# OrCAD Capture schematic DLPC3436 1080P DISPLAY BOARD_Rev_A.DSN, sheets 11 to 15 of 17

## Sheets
11 P15: Actuator Power: size D
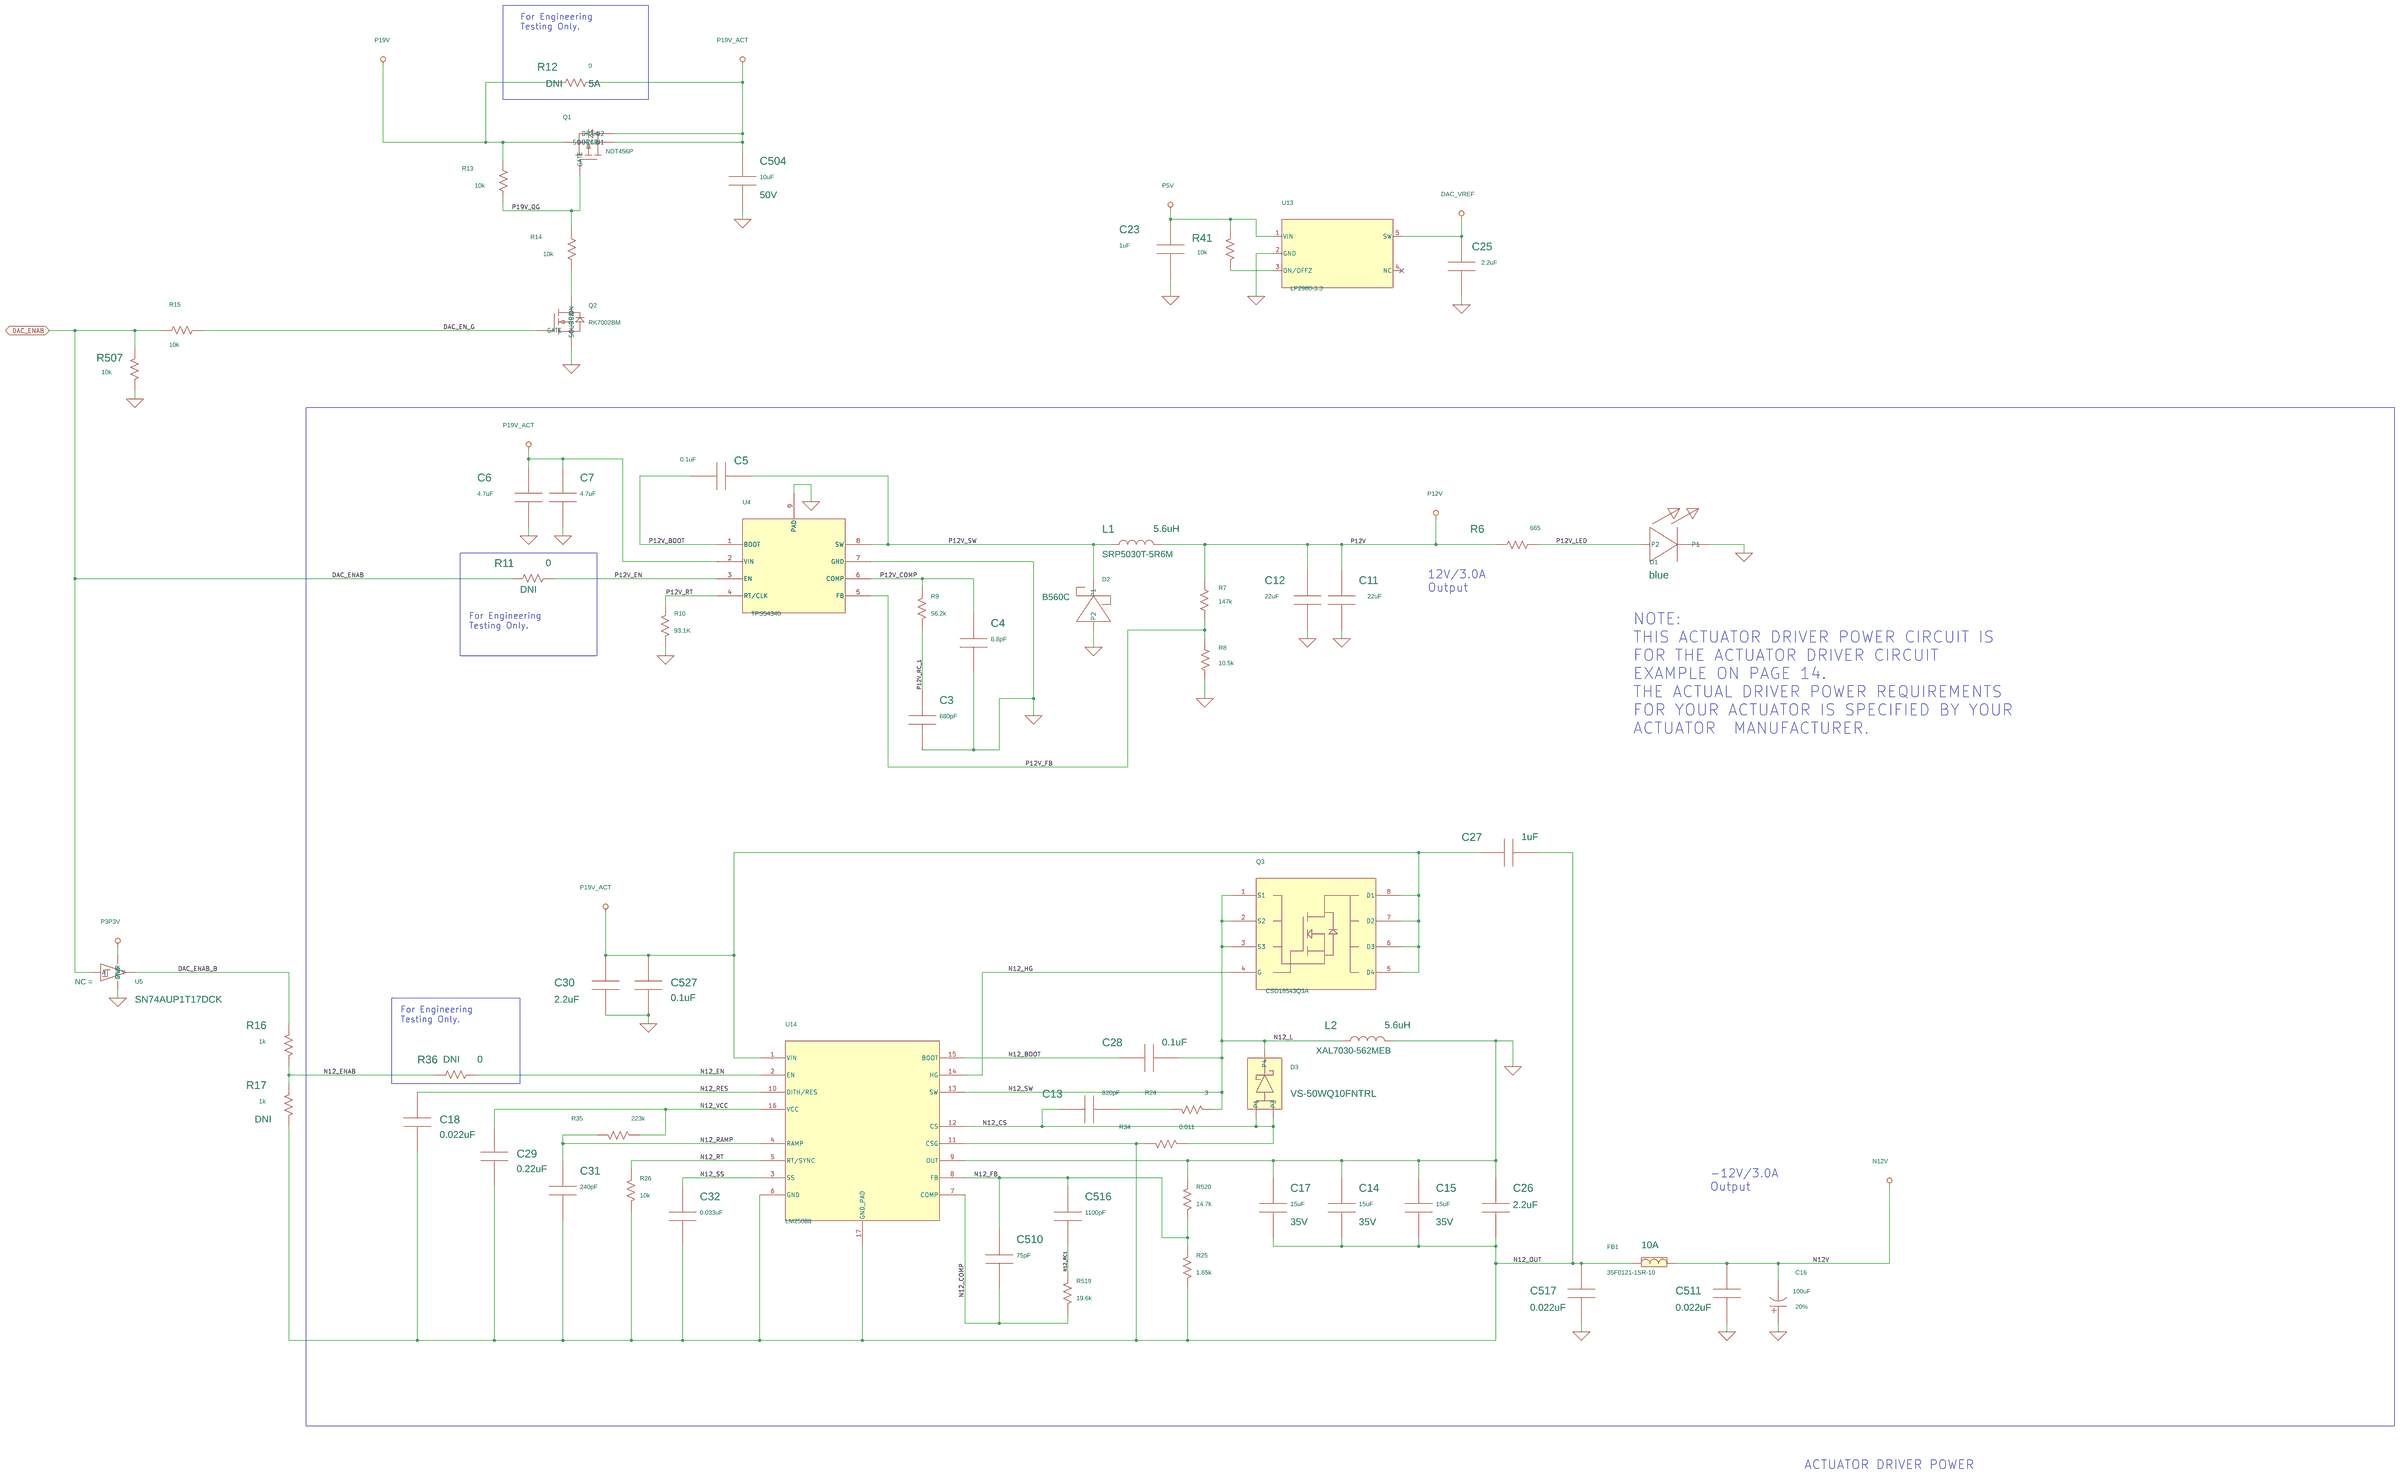
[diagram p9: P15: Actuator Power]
12 P06: Frame Buffer Memory: size D
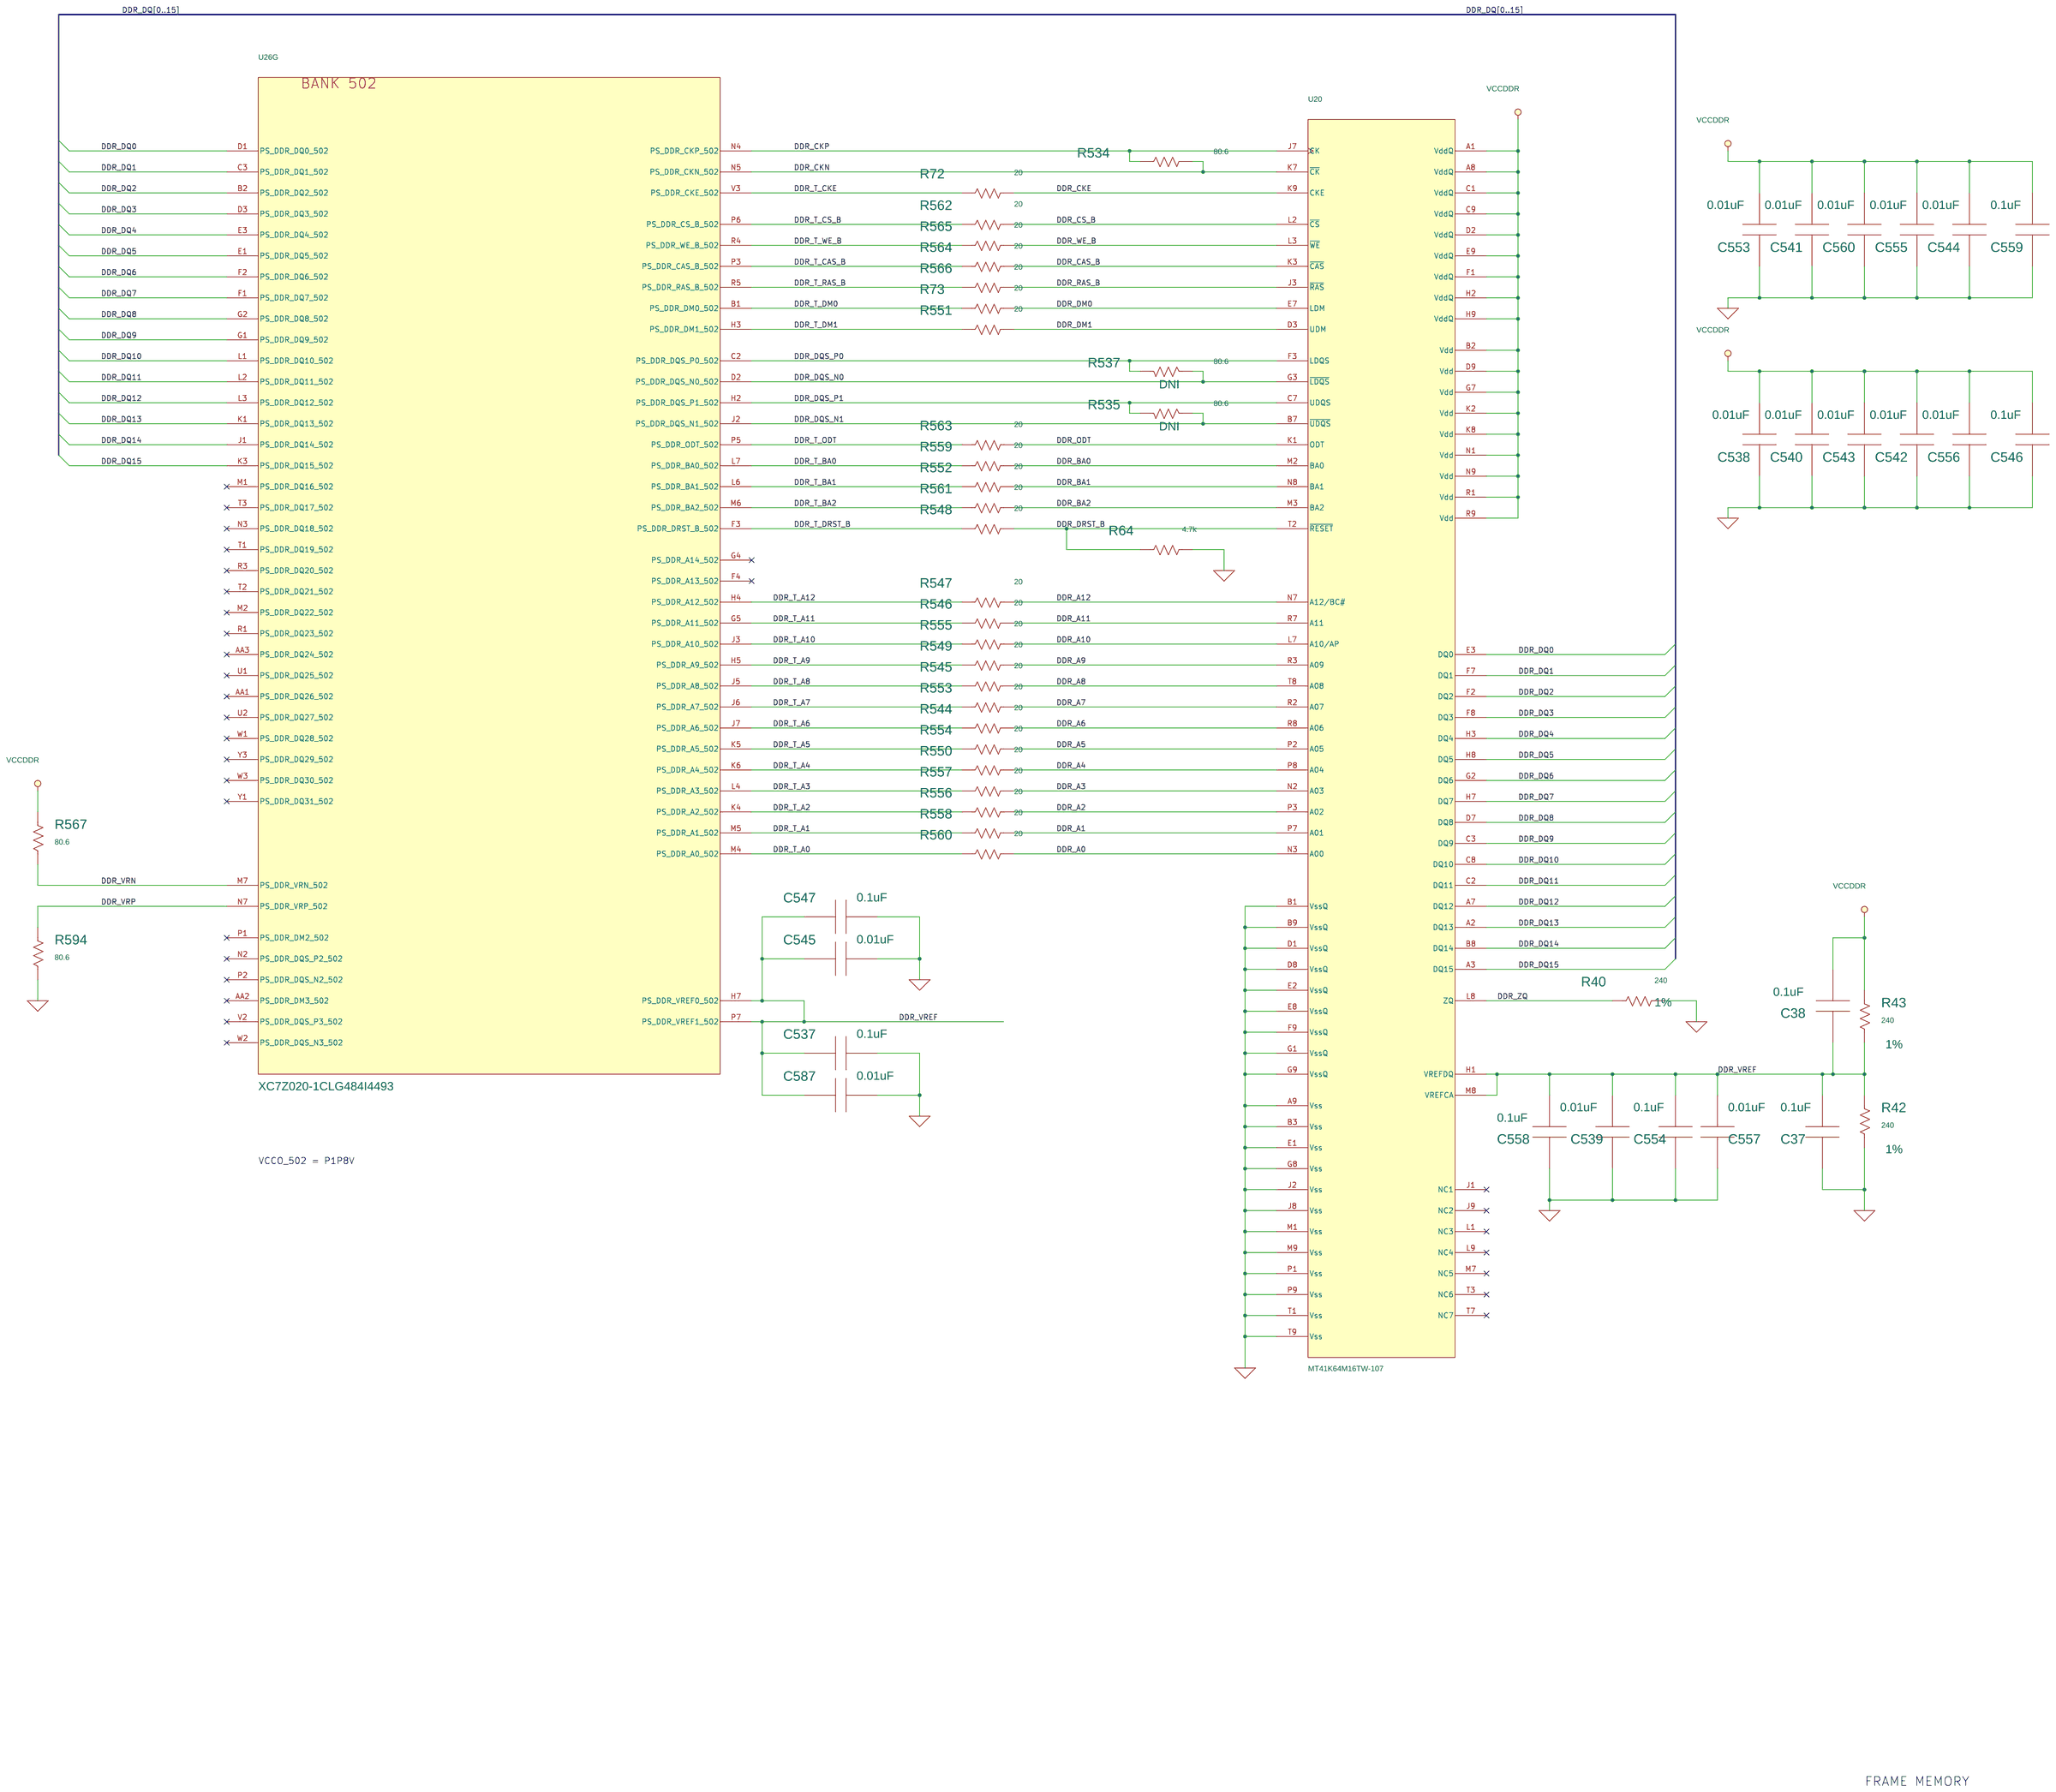
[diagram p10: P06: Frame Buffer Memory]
13 P05: FPGA PDATA Interface: size D
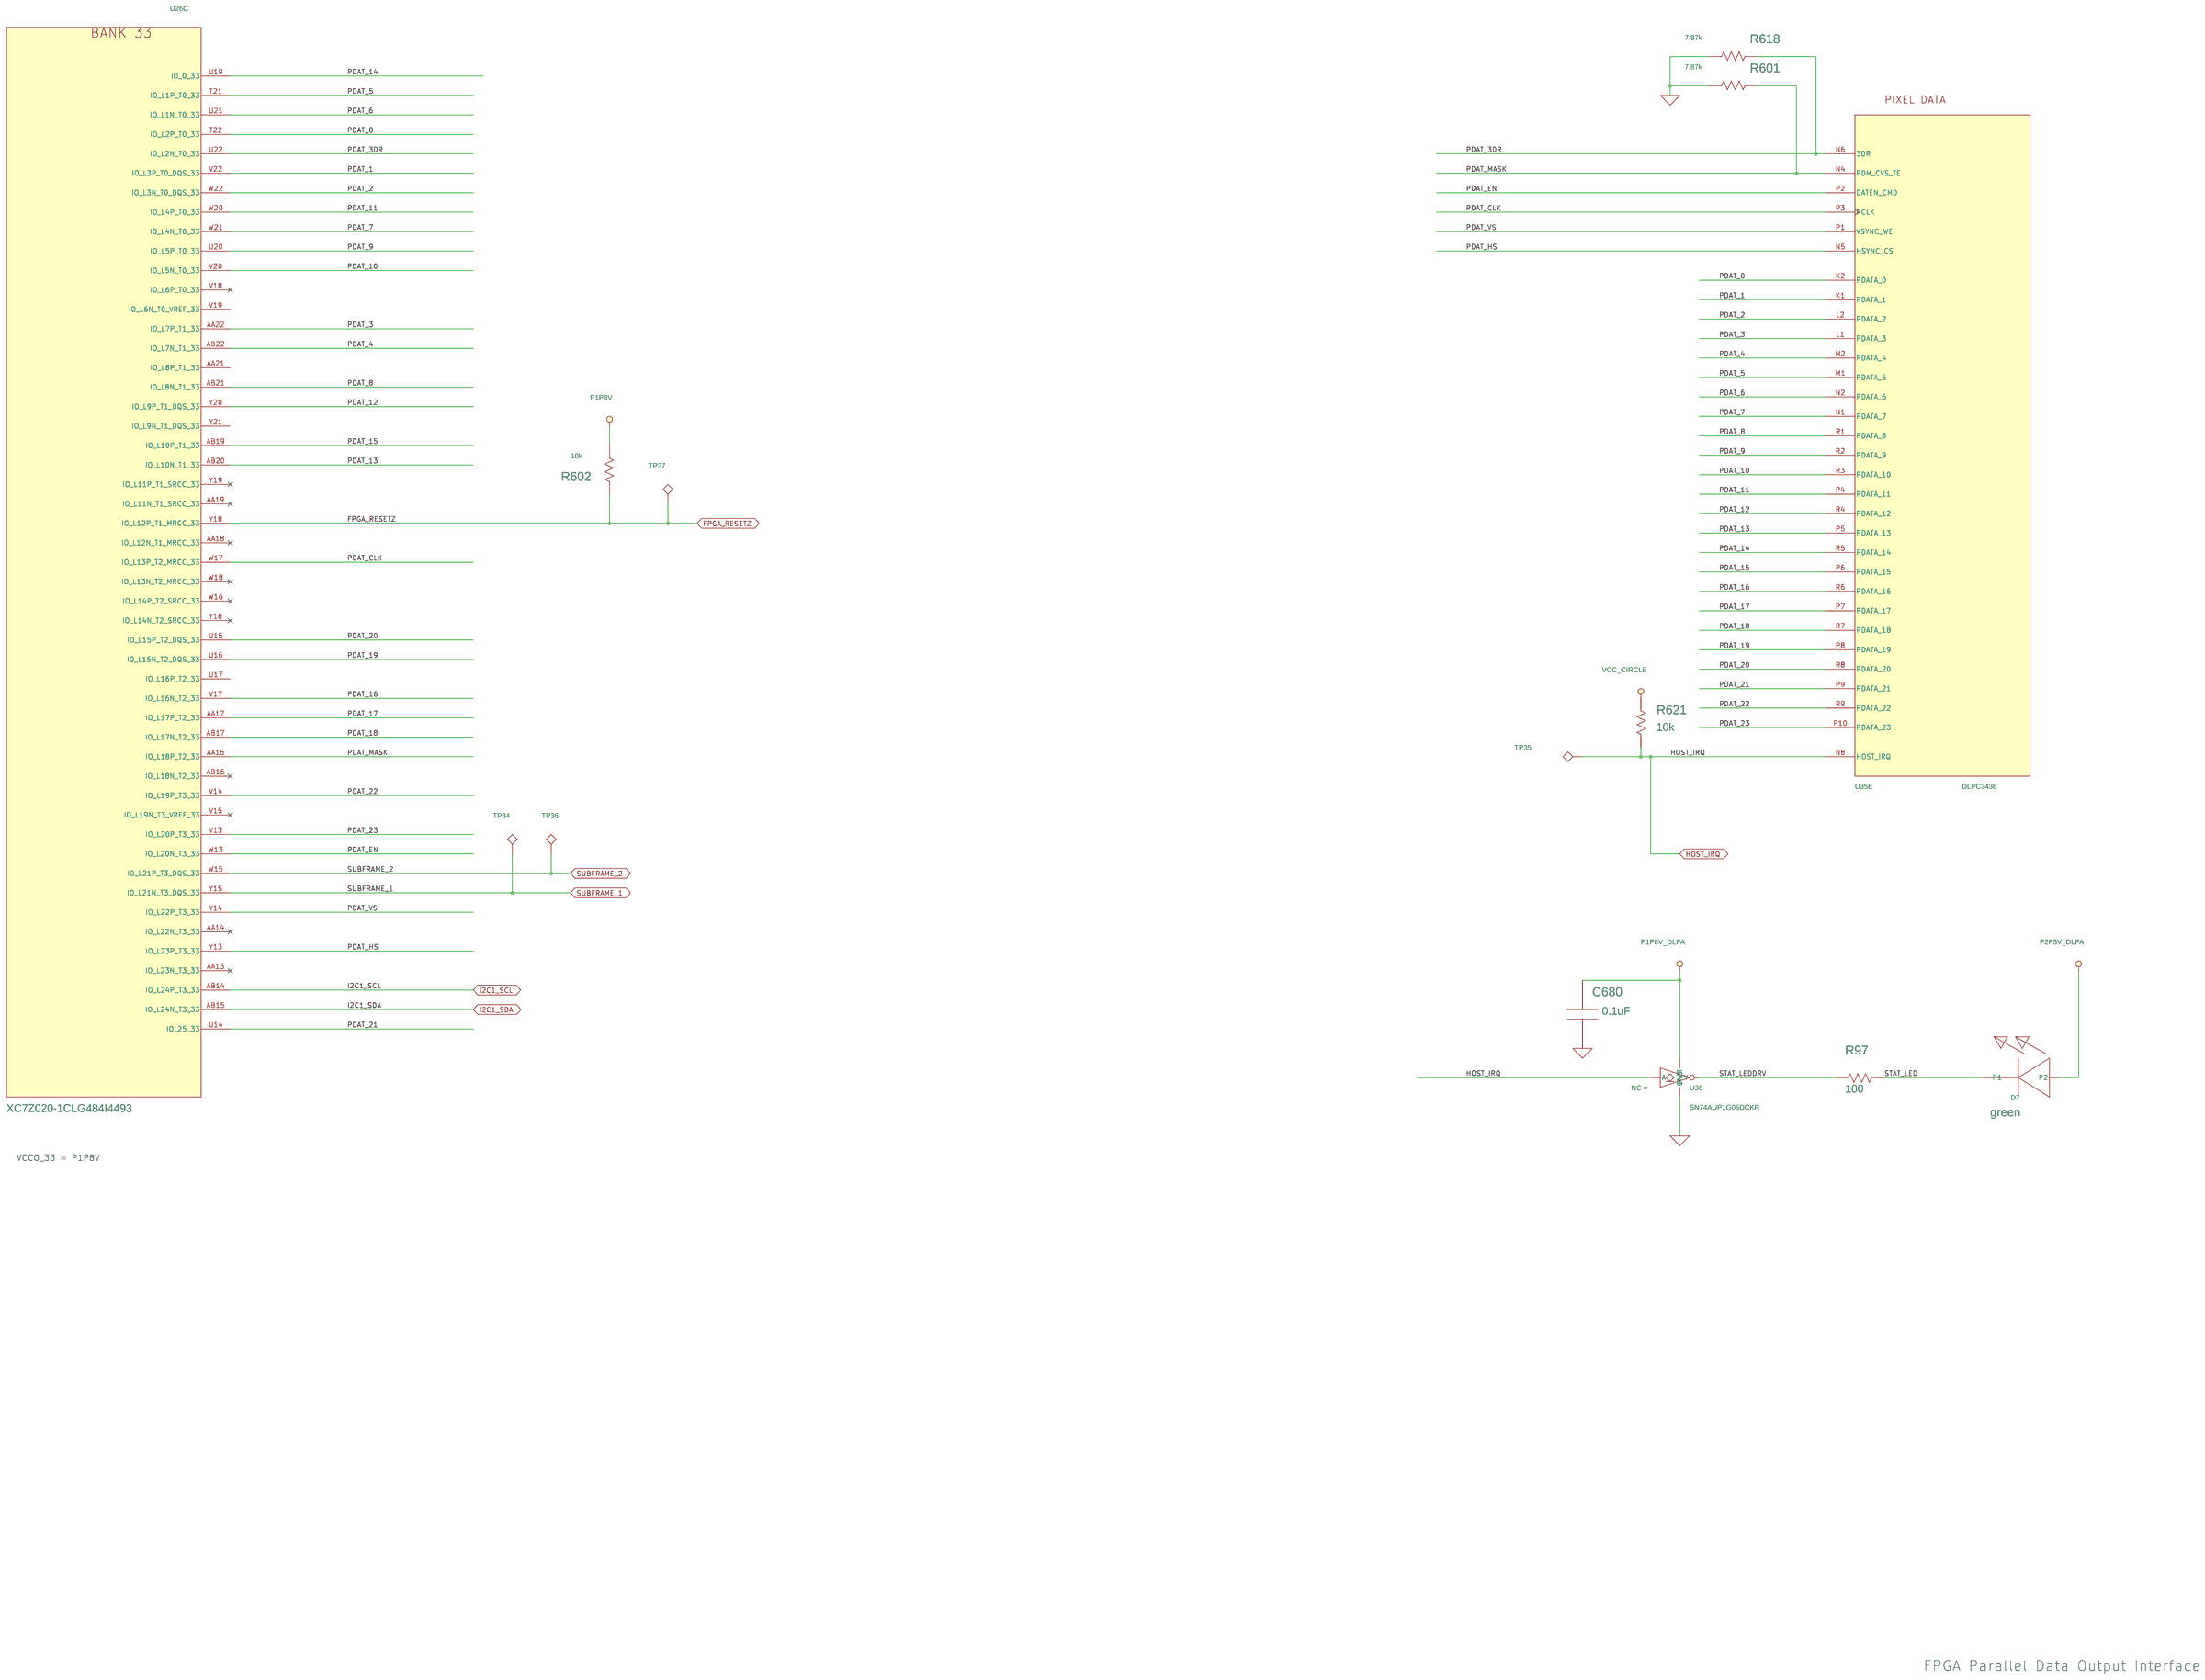
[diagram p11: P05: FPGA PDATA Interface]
14 P04: FPD-Link Video Input: size D
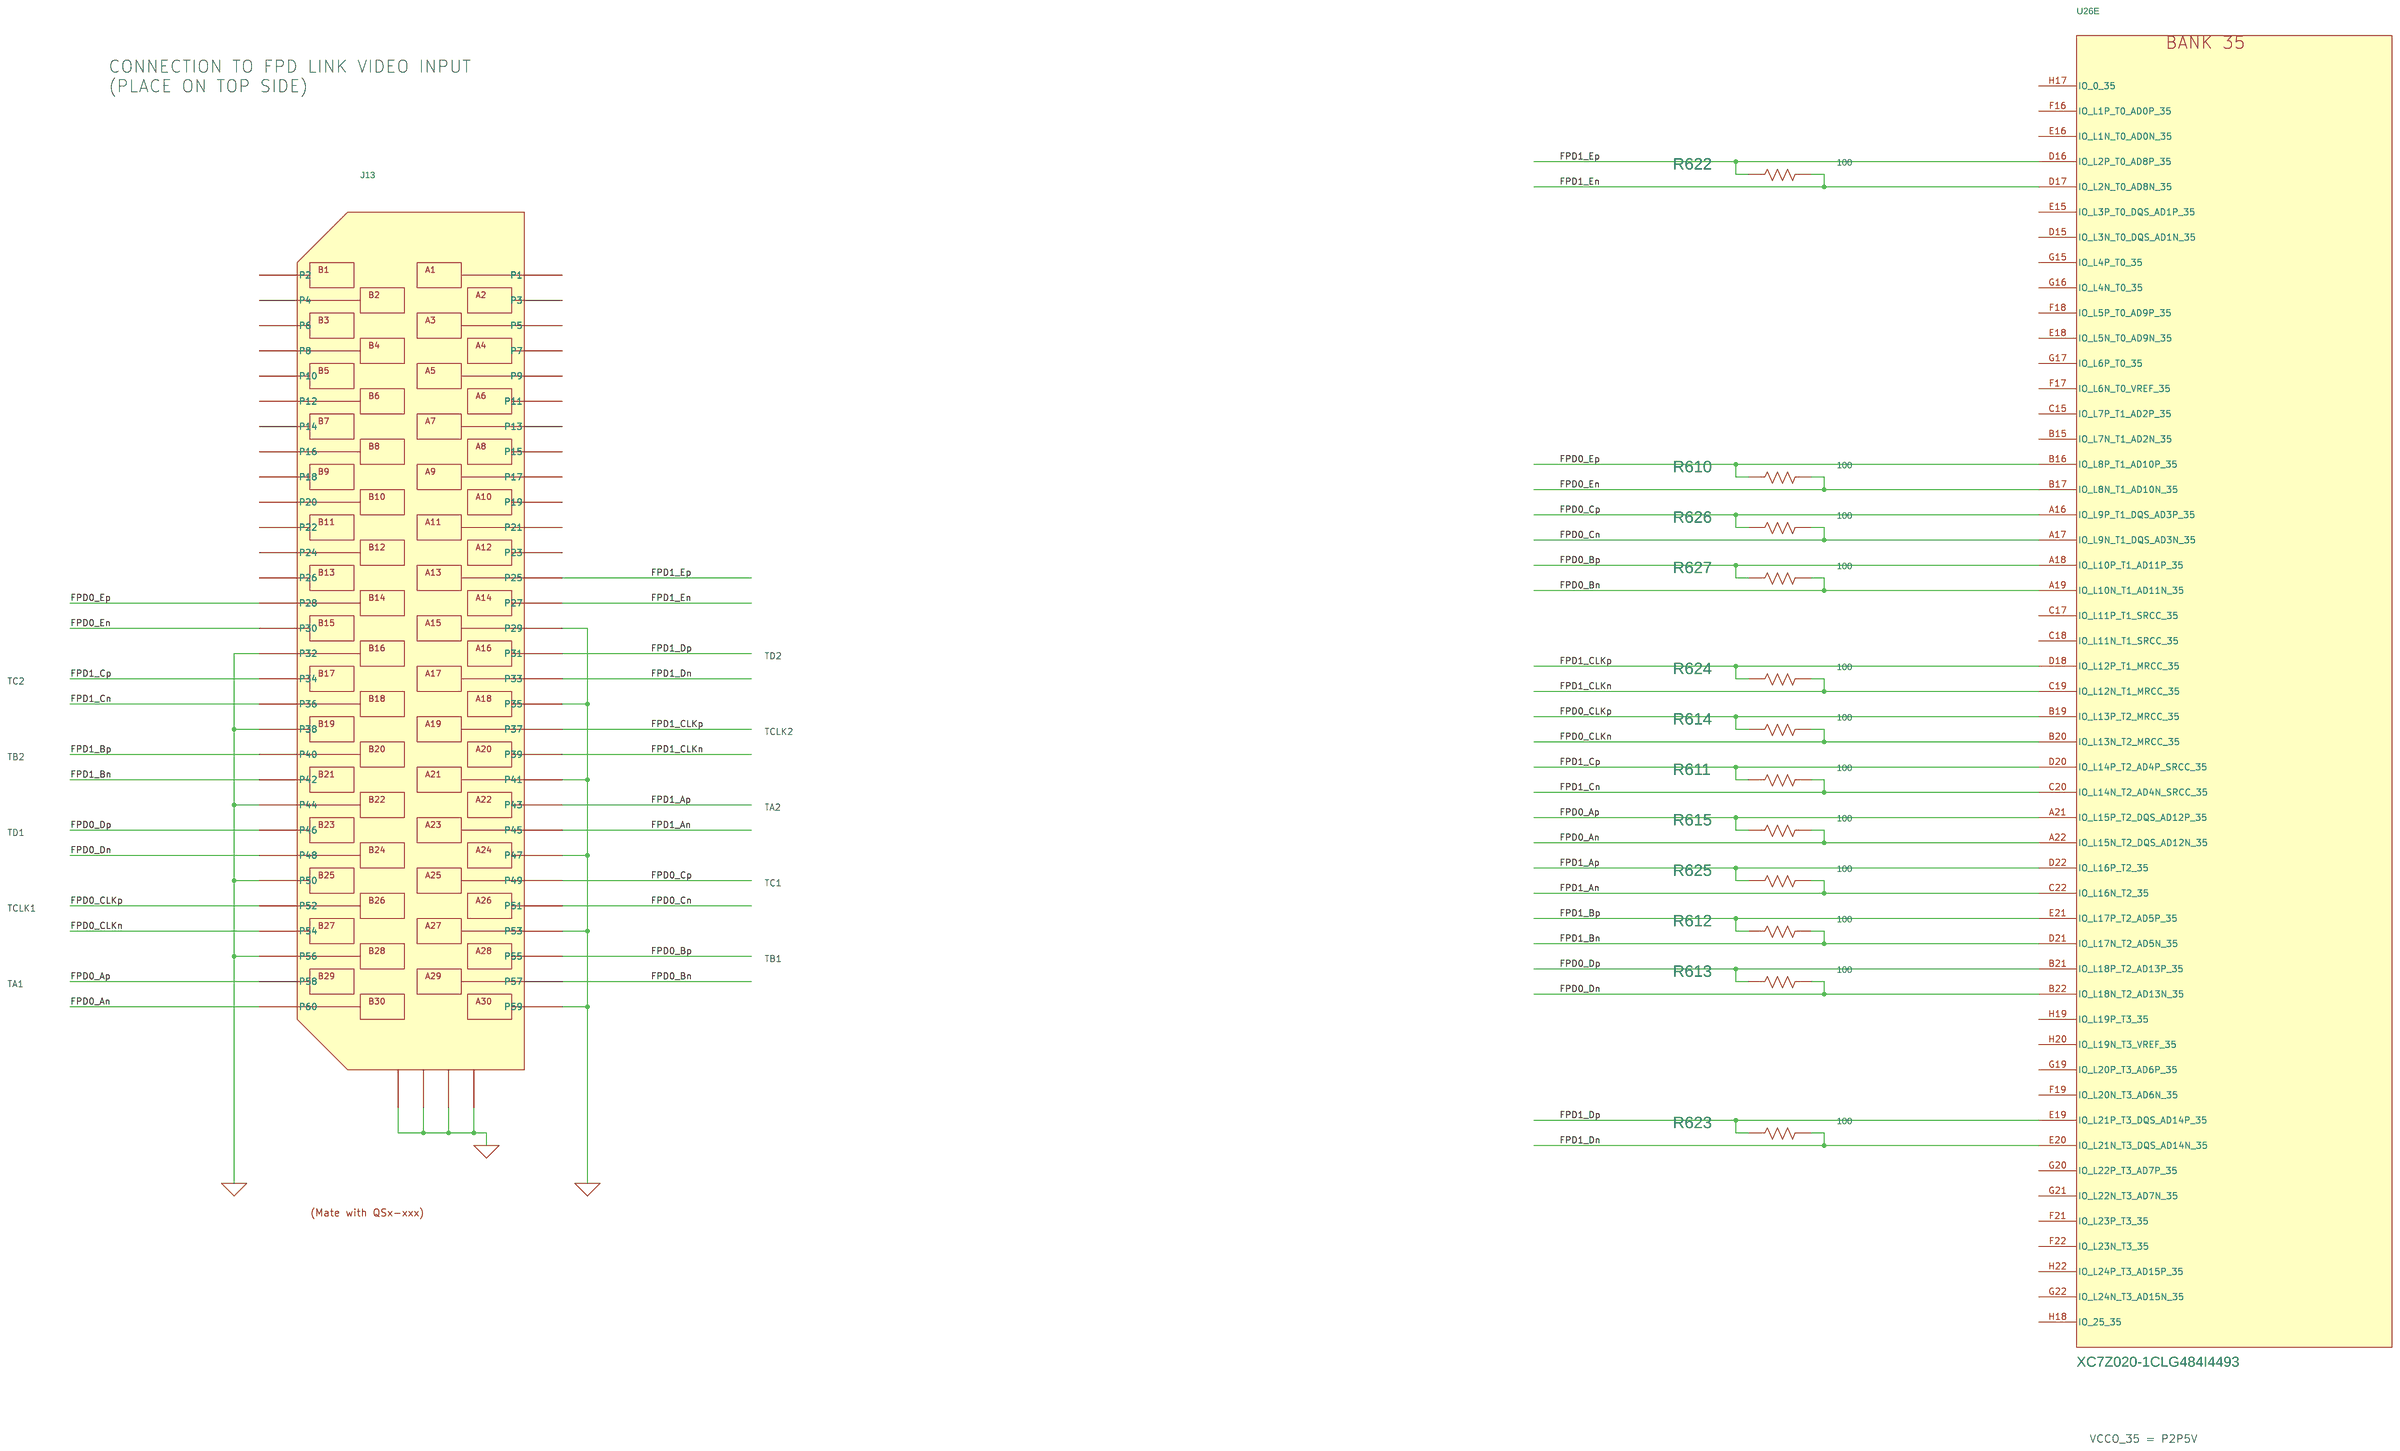
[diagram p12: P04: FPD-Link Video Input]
15 P09: DLPC3436 ASIC & Flash: size D
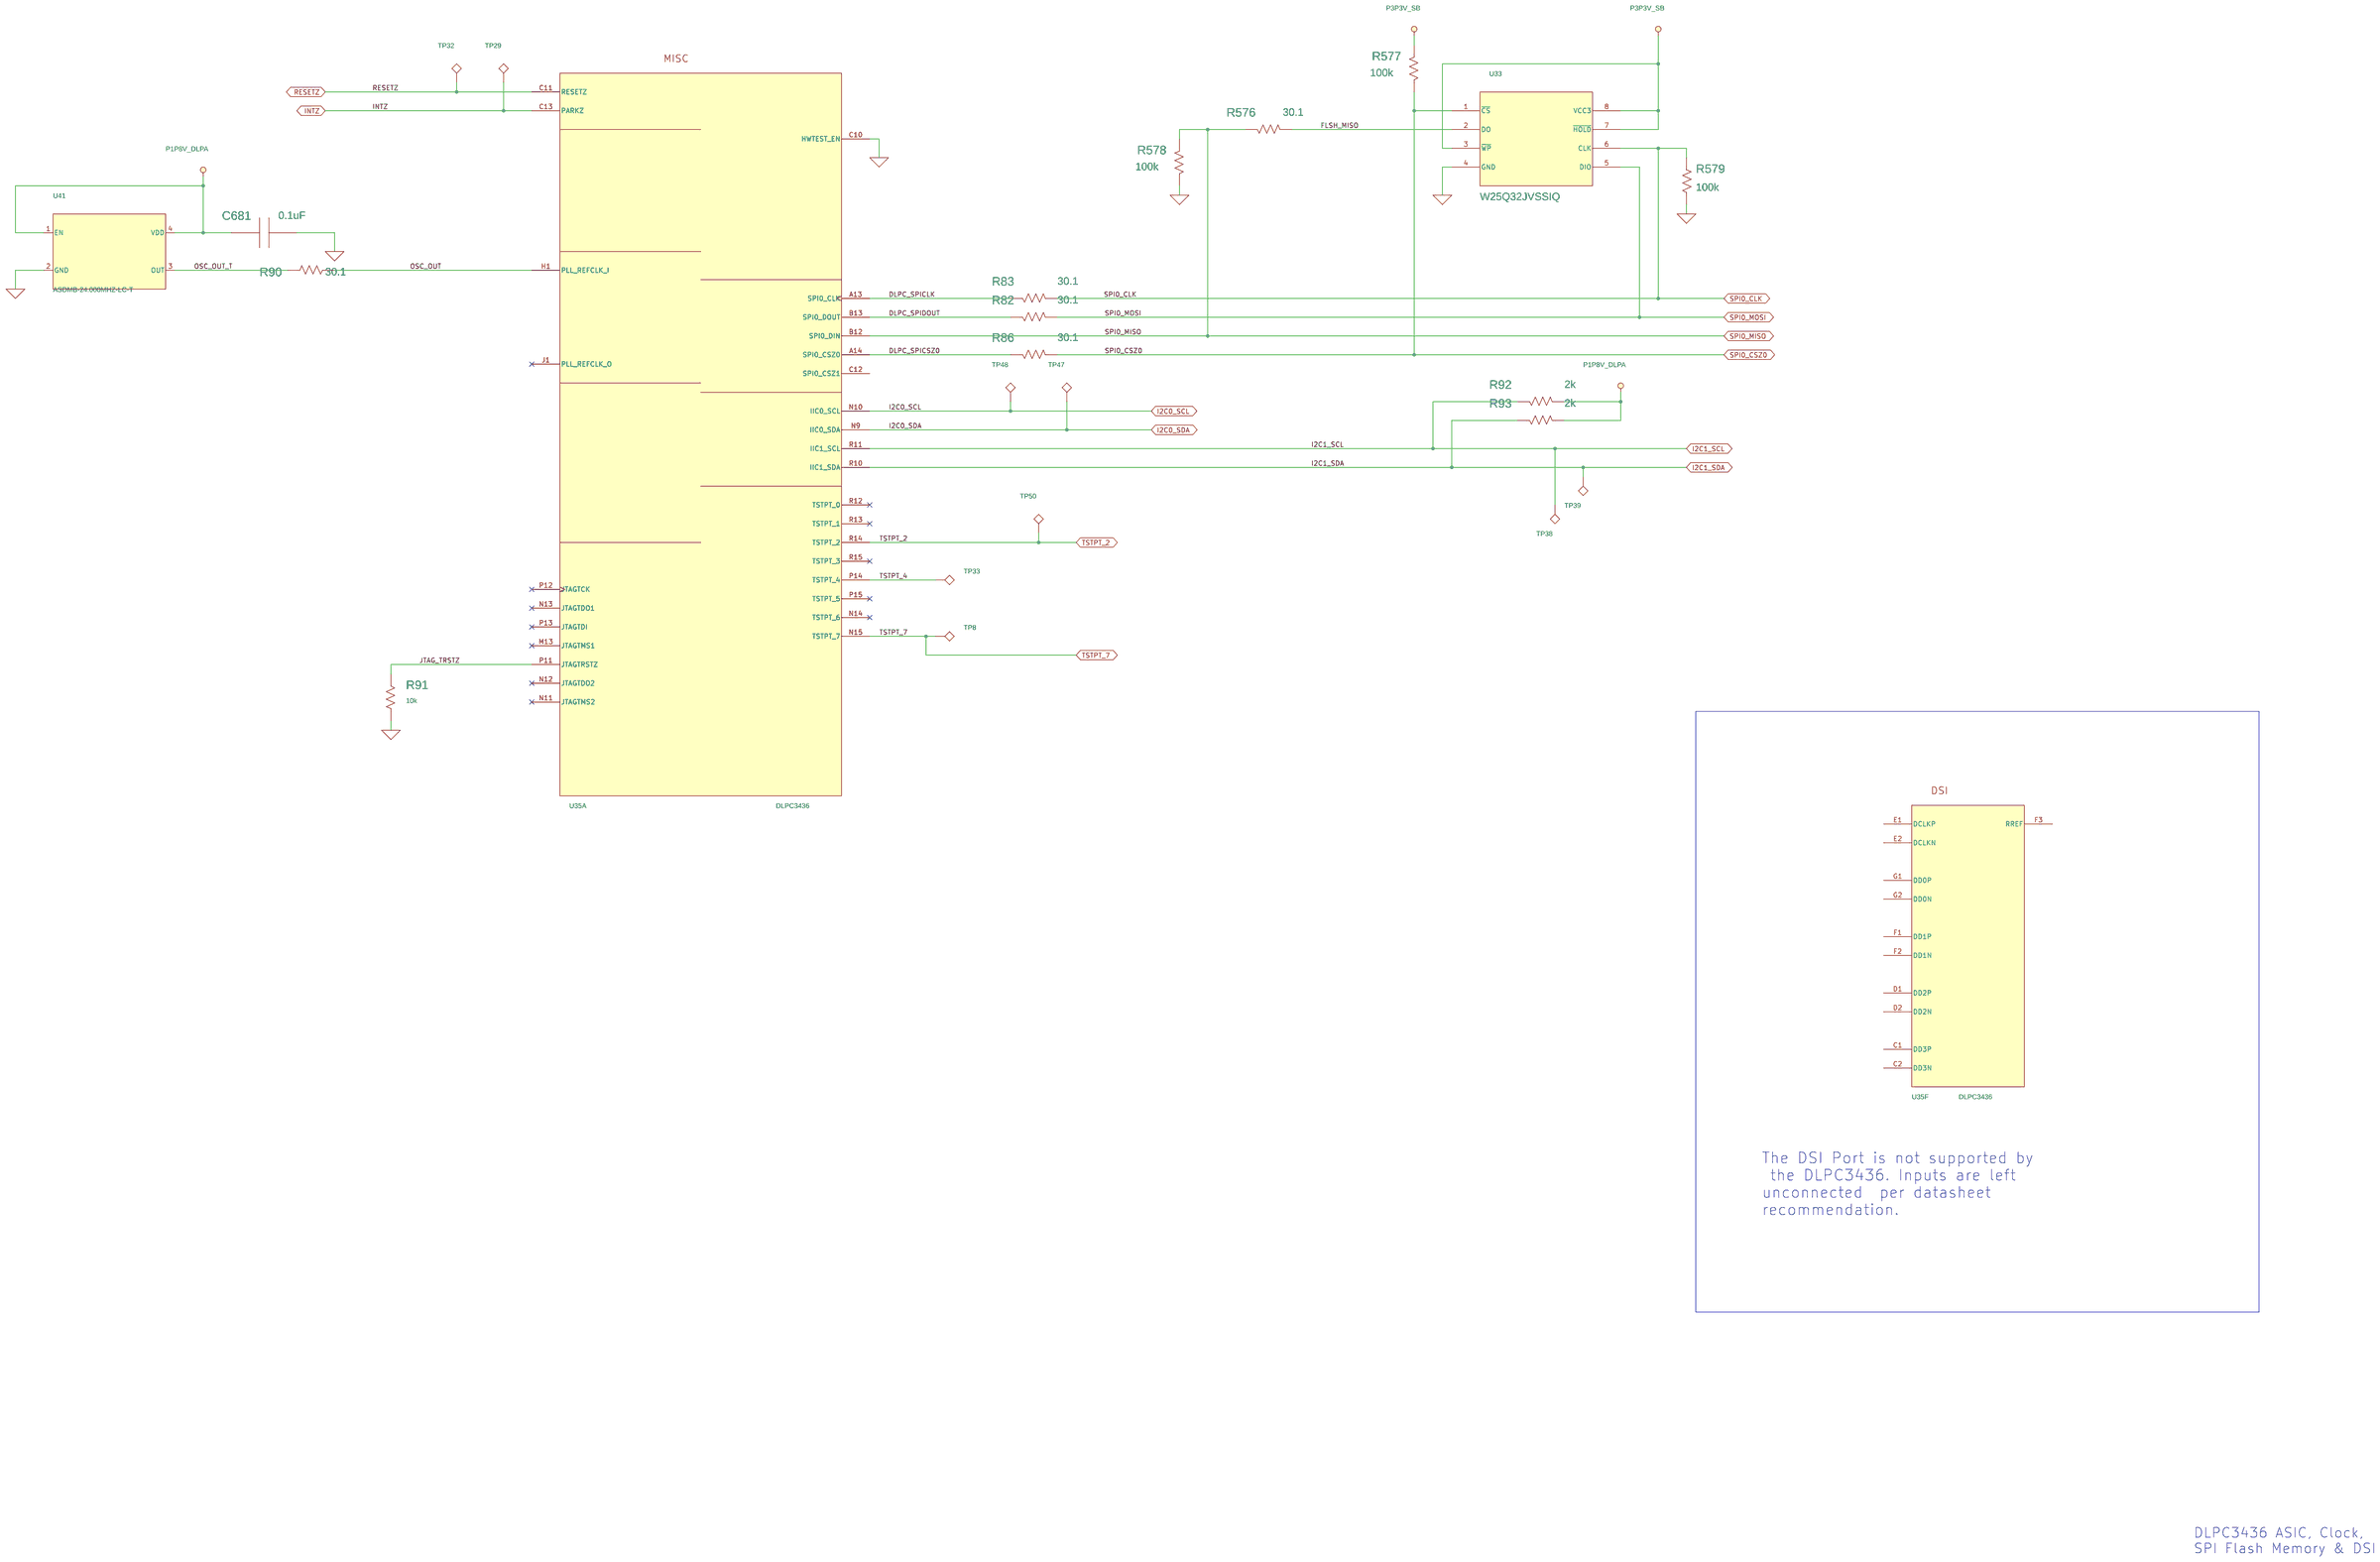
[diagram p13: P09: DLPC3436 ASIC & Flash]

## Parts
sheet P03: Parallel Video Input
U26  XC7Z020-1CLG484I4493  [Xilinx_CLG484]  (sections A,B,C,D,E,F,G,H,I,J)
sheet P04: FPD-Link Video Input
J13  QTH-030-02-L-D-A  [Samtec_QTH-030-xx-x-D-A]
R610  100  [0402]
R611  100  [0402]
R612  100  [0402]
R613  100  [0402]
R614  100  [0402]
R615  100  [0402]
R622  100  [0402]
R623  100  [0402]
R624  100  [0402]
R625  100  [0402]
R626  100  [0402]
R627  100  [0402]
sheet P05: FPGA PDATA Interface
C680  0.1uF  [0402_AVXA]
D7  green  [1206]
R97  100  [0402]
R601  7.87k  [0402]
R602  10k  [0402]
R618  7.87k  [0402]
R621  10k  [0402]
TP34  TP_WHT  [KEYSTONE_TP_MINIATURE]
TP35  TP_WHT  [KEYSTONE_TP_MINIATURE]
TP36  TP_WHT  [KEYSTONE_TP_MINIATURE]
TP37  TP_WHT  [KEYSTONE_TP_MINIATURE]
U36  SN74AUP1G06DCK  [U_5_DCK]
sheet P06: Frame Buffer Memory
C37  0.1uF  [0402_AVXA]
C38  0.1uF  [0402_AVXA]
C537  0.1uF  [0402_AVXA]
C538  0.01uF  [0402]
C539  0.01uF  [0402]
C540  0.01uF  [0402]
C541  0.01uF  [0402]
C542  0.01uF  [0402]
C543  0.01uF  [0402]
C544  0.01uF  [0402]
C545  0.01uF  [0402]
C546  0.1uF  [0402_AVXA]
C547  0.1uF  [0402_AVXA]
C553  0.01uF  [0402]
C554  0.1uF  [0402_AVXA]
C555  0.01uF  [0402]
C556  0.01uF  [0402]
C557  0.01uF  [0402]
C558  0.1uF  [0402_AVXA]
C559  0.1uF  [0402_AVXA]
C560  0.01uF  [0402]
C587  0.01uF  [0402]
R40  240  [0402]
R42  240  [0402]
R43  240  [0402]
R64  4.7k  [0402]
R72  20  [0201_R]
R73  20  [0201_R]
R534  80.6  [0402]
R535  80.6  [0402]
R537  80.6  [0402]
R544  20  [0201_R]
R545  20  [0201_R]
R546  20  [0201_R]
R547  20  [0201_R]
R548  20  [0201_R]
R549  20  [0201_R]
R550  20  [0201_R]
R551  20  [0201_R]
R552  20  [0201_R]
R553  20  [0201_R]
R554  20  [0201_R]
R555  20  [0201_R]
R556  20  [0201_R]
R557  20  [0201_R]
R558  20  [0201_R]
R559  20  [0201_R]
R560  20  [0201_R]
R561  20  [0201_R]
R562  20  [0201_R]
R563  20  [0201_R]
R564  20  [0201_R]
R565  20  [0201_R]
R566  20  [0201_R]
R567  80.6  [0402]
R594  80.6  [0402]
U20  MT41K64M16TW-107  [Micron_96-ball_FBGA-x16_TW]
sheet P09: DLPC3436 ASIC & Flash
C681  0.1uF  [0402_AVXA]
R82  30.1  [0402]
R83  30.1  [0402]
R86  30.1  [0402]
R90  30.1  [0402]
R91  10k  [0402]
R92  2k  [0402]
R93  2k  [0402]
R576  30.1  [0402]
R577  100k  [0402]
R578  100k  [0402]
R579  100k  [0402]
TP8  TP,12mil Drill,32mil Pad  [HOLE_PLATED_12mil_DRILL_32mil_PAD]
TP29  TP40  [TP40]
TP32  TP40  [TP40]
TP33  TP,12mil Drill,32mil Pad  [HOLE_PLATED_12mil_DRILL_32mil_PAD]
TP38  TP,12mil Drill,32mil Pad  [HOLE_PLATED_12mil_DRILL_32mil_PAD]
TP39  TP,12mil Drill,32mil Pad  [HOLE_PLATED_12mil_DRILL_32mil_PAD]
TP47  TP40  [TP40]
TP48  TP40  [TP40]
TP50  TP40  [TP40]
U33  W25Q32JVSSIQ  [SOIC-8_208mil]
U41  24MHz  [ECS-2018_2p5mmx2mm]
sheet P10: DMD Connection
U35  DLPC3436  [DLPC3436_176NFBGA]  (sections A,B,C,D,E,F,G,H)
sheet P15: Actuator Power
C3  680pF  [0402]
C4  6.8pF  [0402]
C5  0.1uF  [0402]
C6  4.7uF  [0603]
C7  4.7uF  [0603]
C11  22uF  [0805]
C12  22uF  [0805]
C13  820pF  [0603]
C14  15uF  [1206]
C15  15uF  [1206]
C16  100uF  [sizeD_260x260mil_radial_can]
C17  15uF  [1206]
C18  0.022uF  [0603]
C23  1uF  [0603]
C25  2.2uF  [0805]
C26  2.2uF  [0805]
C27  1uF  [0603]
C28  0.1uF  [0805]
C29  0.22uF  [0805]
C30  2.2uF  [0805]
C31  240pF  [0805]
C32  0.033uF  [0402]
C504  10uF  [1210]
C510  75pF  [0805]
C511  0.022uF  [0805]
C516  1100pF  [0603]
C517  0.022uF  [0805]
C527  0.1uF  [0805]
D1  blue  [1206]
D2  B560C  [SMC]
D3  VS-50WQ10FNTRL  [VS_DPAK_TO-252AA]
FB1  35F0121-1SR-10  [Laird_35F0121-1S]
L1  5.6uH  [Bourns_SRP5030T]
L2  5.6uH  [Coilcraft_XAL70300]
Q1  NDT456P  [SOT223_NDT456P]
Q2  RK7002BM  [SOT23-3_BSS138L]
Q3  CSD18543Q3A  [NexFET_8SON_3X3MM]
R6  665  [0805]
R7  147k  [0402]
R8  10.5k  [0402]
R9  56.2k  [0402]
R10  93.1K  [0402]
R11  0  [0402]
R12  0  [1210]
R13  10k  [0603]
R14  10k  [0603]
R15  10k  [0603]
R16  1k  [0402]
R17  1k  [0402]
R24  3  [0603]
R25  1.65k  [0402]
R26  10k  [0603]
R34  0.011  [1206]
R35  223k  [0805]
R36  0  [0402]
R41  10k  [0402]
R507  10k  [0402]
R519  19.6k  [0805]
R520  14.7k  [0402]
U4  TPS54340  [HSOIC8_DDA_R-PDSO-G8]
U5  SN74AUP1T17DCK  [U_5_DCK]
U13  LP2980-3.3  [SOT23-5_DBV]
U14  LM25088  [HTSSOP16_PWP]

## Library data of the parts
U26 = TIDLP,XPR_FPGA,Zynq-7020new_0: DigiKey: ---; DigiReel: ---; Family: processor; Index PN: 1304; Lead Style: SMT; MFG: Xilinx; Type: dlp; Vendor: Xilinx
J13 = EM,CONN,60P,QTx: DigiKey: SAM8186-ND; Family: electro/mechanical; Index PN: 1197; Lead Style: SMT; MFG: Samtec; Part Specific: CONN HEADER HS .5MM 60POS DL AU (stacking ht 8mm); Pin Cnt: 60; Pin Spacing: 0.5mm; Row Cnt: 2; Type: connector; Vendor: Samtec
R97 R610-R615 R622-R627 = PAS,R,large: DigiKey: P100LCT-ND; DigiReel: P100LDKR-ND; Family: passive; Index PN: 690; Lead Style: SMT; MFG: Panasonic; Material: chip; P/D_NUM: ERJ-2RKF1000X; Part Number: ERJ-2RKF1000X; Part Specific: RES 100 OHM 1/10W 1% 0402 SMD; Power: 1/16W; TOLERANCE: 1%; Type: resistor; VENDOR: Panasonic; VPC: 1/16W
C37 C38 C537 C546 C547 C554 C558 C559 C680 C681 = PAS,CAP,NP,large: DigiKey: 445-4952-1-ND; DigiReel: 445-4952-6-ND; Family: passive; Index PN: 681; Lead Style: SMT; MFG: TDK; Material: x7r; P/D_NUM: C1005X7R1C104K050BC; Part Number: C1005X7R1C104K050BC; Part Specific: CAP CER .1UF 16V X7R 0402; TOLERANCE: 10%; Type: capacitor; VENDOR: TDK; VPC: 16V
D7 = PAS,DIODE,LED,large: DigiKey: 67-1357-1-ND; DigiReel: 67-1357-6-ND; Family: passive; Index PN: 31; Install: Y; Lead Style: SMT; MFG: Lumex; P/D_NUM: SML-LX1206GC-TR; Part Number: SML-LX1206GC-TR; Part Specific: LED 565NM WTR CLR GREEN 1206 SMD; Type: diode,led; VENDOR: Lumex
R601 R618 = PAS,R,large: DigiKey: P7.87KLCT-ND; DigiReel: P7.87KLDKR-ND; Family: passive; Index PN: 1175; Lead Style: SMT; MFG: Panasonic; Material: chip; P/D_NUM: ERJ-2RKF7871X; Part Number: ERJ-2RKF7871X; Part Specific: RES 7.87K OHM 1/10W 1% 0402 SMD; Type: resistor; VENDOR: Panasonic; VPC: 1/10W
R602 = PAS,R,large: DigiKey: P10.0KLCT-ND; DigiReel: P10.0KLDKR-ND; Family: passive; Index PN: 680; Install: Y; Lead Style: SMT; MFG: Panasonic; Material: chip; P/D_NUM: ERJ-2RKF1002X; Part Number: ERJ-2RKF1002X; Part Specific: RES SMD 10K OHM 1% 1/10W 0402; Power: 1/16W; TOLERANCE: 1%; Type: resistor; VENDOR: Panasonic; VPC: 1/16W
R621 = PAS,R,large: DigiKey: P10.0KLCT-ND; DigiReel: P10.0KLDKR-ND; Family: passive; Index PN: 680; Install: Y; Lead Style: SMT; MFG: Panasonic; Material: chip; P/D_NUM: ERJ-2RKF1002X; Part Number: ERJ-2RKF1002X; Part Specific: RES SMD 10K OHM 1% 1/10W 0402; Power: 1/16W; TOLERANCE: 1%; Type: resistor; VPC: 1/16W; Vendor: Panasonic
TP34-TP37 = EM,TERM,TESTPOINT: DigiKey: 36-5002-ND; DigiReel: ---; Family: electro/mechanical; Install: DNI; Lead Style: TH; MFG: Keystone; P/D_NUM: 5002; Part Number: 5002; Part Specific: TEST POINT PC MINI .040inD WHITE; Type: terminal; Vendor: Keystone
U36 = LOG,INV,OPENDRN,SN74AUP1G06DCK: DigiKey: 296-17562-1-ND; DigiReel: 296-17562-6-ND; Family: logic; Index PN: 1026; Lead Style: SMT; MFG: Texas Instruments; P/D_NUM: SN74AUP1G06DCKR; Part Number: SN74AUP1G06DCKR; Part Specific: IC INVERTER SINGLE 1INPUT SC705, open drain; Type: buffer
C538-C545 C553 C555-C557 C560 C587 = PAS,CAP,NP,large: DigiKey: 445-1262-1-ND; DigiReel: 445-1262-6-ND; Family: passive; Index PN: 908; Lead Style: SMT; MFG: TDK; Material: x7r; P/D_NUM: C1005X7R1C103K; Part Number: C1005X7R1C103K; Part Specific: CAP CER 10000PF 16V X7R 10% 0402; TOLERANCE: 10%; Type: capacitor; VENDOR: TDK; VPC: 16V
R40 R42 R43 = PAS,R,large: DigiKey: P240LCT-ND; DigiReel: P240LDKR-ND; Family: passive; Index PN: 1303; Lead Style: SMT; MFG: Panasonic; P/D_NUM: ERJ-2RKF2400X; Part Number: ERJ-2RKF2400X; Part Specific: RES SMD 240 OHM 1% 1/10W 0402; TOLERANCE: 1%; Type: resistor; VENDOR: Panasonic; VPC: 1/16W
R64 = PAS,R,large: DigiKey: P4.70KLCT-ND; DigiReel: P4.70KLDKR-ND; Family: passive; Index PN: 1219; Lead Style: SMT; MFG: Panasonic; P/D_NUM: ERJ-2RKF4701X; Part Number: ERJ-2RKF4701X; Part Specific: RES 4.7K OHM 1/10W 1% 0402 SMD; Type: resistor; VENDOR: Panasonic; VPC: 1/16W
R72 R73 R544-R566 = PAS,R,large: DigiKey: YAG2500CT-ND; DigiReel: YAG2500DKR-ND; Family: passive; Install: Y; Lead Style: SMT; MFG: Yageo; P/D_NUM: RC0201FR-0720RL; Part Number: RC0201FR-0720RL; Part Specific: RES SMD 20 OHM 1% 1/20W 0201; Type: resistor; VENDOR: Yageo; VPC: 1/20W
R534 R567 R594 = PAS,R,large: DigiKey: P80.6LCT-ND; DigiReel: P80.6LDKR-ND; Family: passive; Install: Y; Lead Style: SMT; MFG: Panasonic; Material: chip; P/D_NUM: ERJ-2RKF80R6X; Part Number: ERJ-2RKF80R6X; Part Specific: RES 80.6 OHM 1% 1/10W 0402 SMD; Power: 1/10W; TOLERANCE: 1%; Type: resistor; VENDOR: Panasonic; VPC: 1/10W
R535 R537 = PAS,R,large: DigiKey: P80.6LCT-ND; DigiReel: P80.6LDKR-ND; Family: passive; Install: DNI; Lead Style: SMT; MFG: Panasonic; Material: chip; P/D_NUM: ERJ-2RKF80R6X; Part Number: ERJ-2RKF80R6X; Part Specific: RES 80.6 OHM 1% 1/10W 0402 SMD; Power: 1/10W; TOLERANCE: 1%; Type: resistor; VENDOR: Panasonic; VPC: 1/10W
U20 = MEM,SDRAM,DDR3,8Mx16x4banks_0: DigiKey: 557-1765-ND; DigiReel: ---; Family: memory; Index PN: 1302; Lead Style: SMT; MFG: Micron; P/D_NUM: MT41K64M16TW-107:J; Part Number: MT41K64M16TW-107:J; Part Specific: IC DDR3 SDRAM 1Gb (64MX16) 96FBGA; Temp: I; Type: sdram,ddr3; Vendor: Micron
R82 R83 R86 R90 R576 = PAS,R,large: DigiKey: P30.1LCT-ND; DigiReel: P30.1LDKR-ND; Family: passive; Index PN: 976; Lead Style: SMT; MFG: Panasonic; Material: chip; P/D_NUM: ERJ-2RKF30R1X; Part Number: ERJ-2RKF30R1X; Part Specific: RES 30.1 OHM 1/16W 1% 0402 SMD; Power: 1/16W; TOLERANCE: 1%; Type: resistor; VENDOR: Panasonic; VPC: 1/16W
R41 R91 R507 = PAS,R,large: DigiKey: P10.0KLCT-ND; DigiReel: P10.0KLDKR-ND; Family: passive; Index PN: 680; Lead Style: SMT; MFG: Panasonic; Material: chip; P/D_NUM: ERJ-2RKF1002X; Part Number: ERJ-2RKF1002X; Part Specific: RES SMD 10K OHM 1% 1/10W 0402; Power: 1/16W; TOLERANCE: 1%; Type: resistor; VENDOR: Panasonic; VPC: 1/16W
R92 R93 = PAS,R,large: DigiKey: P2.00KLCT-ND; DigiReel: P2.00KLDKR-ND; Family: passive; Index PN: 1348; Lead Style: SMT; MFG: Panasonic; P/D_NUM: ERJ-2RKF2001X; Part Number: ERJ-2RKF2001X; Part Specific: RES SMD 2K OHM 1% 1/10W 0402; Power: 1%; Type: resistor; VENDOR: Panasonic; VPC: 1/16W
R577-R579 = PAS,R,large: DigiKey: 541-100KLCT-ND; DigiReel: 541-100KLDKR-ND; Family: passive; Index PN: 712; Lead Style: SMT; MFG: Vishay/Dale; Material: chip; P/D_NUM: CRCW0402100KFKED; Part Number: CRCW0402100KFKED; Part Specific: RES 100K OHM 1/10W 1% 0402 SMD; Power: 1/16W; TOLERANCE: 1%; Type: resistor; VENDOR: Vishay/Dale; VPC: 1/16W
TP8 TP33 TP38 TP39 = EM,TERM,TESTPOINT: Family: board feature; Index PN: 122; Install: DNI; MFG: -- NOT A PART --; Type: hole,plated; Vendor: -- NOT A PART --
TP29 TP32 TP47 TP48 TP50 = EM,TERM,TESTPOINT: DigiKey: ---; DigiReel: ---; Family: board feature; Index PN: 995; Install: DNI; MFG: -- NOT A PART --; Type: hole,plated; Vendor: -- NOT A PART --
U33 = MEM,FLASH,SERIAL,W25XxxALxNIG: DigiKey: W25Q32JVSSIQ-ND; DigiReel: ---; Family: memory; Install: Y; Lead Style: SMT; MFG: Winbond; Part Specific: IC FLASH 32M SPI 133MHZ 8SOIC; Type: flash, spi; VPC: 2.7-3.6V
U41 = ANA,OSC,4P,2X: DigiKey: 535-11728-1-ND; DigiReel: 535-11728-6-ND; Family: analog; Index PN: 1259; Install: Y; Lead Style: SMT; MFG: Abracon; P/D_NUM: ASDMB-24.000MHZ-LC-T; Part Number: ASDMB-24.000MHZ-LC-T; Part Specific: OSC MEMS 24.000MHZ CMOS SMD 1.8V-3.3V; Type: oscillator; VPC: 1.8V-3.3V; Vendor: Abracon
U35 = TIDLP,DPP3430: DigiKey: ---; DigiReel: ---; Family: processor; Lead Style: SMT; MFG: Texas Instruments; P/D_NUM: DLPC3436CZVBR; Part Number: DLPC3436CZVBR; Part Specific: DLP PICO CONTROLLER DLPC3436 176NFBGA; Type: dlp; Vendor: Texas Instruments; Install: Y; SPLIT_INST: TRUE
C3 = PAS,CAP,NP,large: DigiKey: 490-3240-1-ND; DigiReel: 490-3240-6-ND; Family: passive; Lead Style: SMT; MFG: Murata; Material: x7r; P/D_NUM: GRM1555C1H681JA01D; Part Number: GRM1555C1H681JA01D; Part Specific: CAP CER 680PF 50V 5% C0G/NP0 0402; Type: capacitor; VENDOR: Murata; VPC: 50V; Voltage: 50V
C4 = PAS,CAP,NP,large: DigiKey: 490-14425-1-ND; DigiReel: 490-14425-6-ND; Family: passive; Lead Style: SMT; MFG: Murata; Material: npo; P/D_NUM: GCM1555C1H6R8BA16D; Part Number: GCM1555C1H6R8BA16D; Part Specific: CAP CER 6.8PF 50V NP0 0402; TOLERANCE: 0.1pF; Type: capacitor; VENDOR: Murata; VPC: 50V; Voltage: 50V
C5 = PAS,CAP,NP,large: DigiKey: 445-5942-1-ND; DigiReel: 445-5942-6-ND; Family: passive; Index PN: 1280; Lead Style: SMT; MFG: TDK; Material: x5r; P/D_NUM: C1005X5R1H104K050BB; Part Number: C1005X5R1H104K050BB; Part Specific: CAP CER 0.1UF 50V 10% X5R 0402; TOLERANCE: 10%; Type: capacitor; VENDOR: TDK; VPC: 50V; Voltage: 50V
C6 C7 = PAS,CAP,NP,large: DigiKey: 490-7205-1-ND; DigiReel: 490-7205-6-ND; Family: passive; Lead Style: SMT; MFG: Murata; Material: X5R; P/D_NUM: GRM188R6YA475KE15D; Part Number: GRM188R6YA475KE15D; Part Specific: CAP CER 4.7UF 35V 10% X5R 0603; TOLERANCE: 10%; Type: capacitor; VENDOR: Murata; VPC: 35V; Voltage: 35V
C11 C12 = PAS,CAP,NP,large: DigiKey: 445-14428-1-ND; DigiReel: 445-14428-6-ND; Family: passive; Lead Style: SMT; MFG: TDK; Material: x5r; P/D_NUM: C2012X5R1V226M125AC; Part Number: C2012X5R1V226M125AC; Part Specific: CAP CER 22UF 35V 20% X5R 0805; TOLERANCE: 20%; Type: capacitor; VENDOR: TDK; VPC: 35V; Voltage: 35V
C13 = PAS,CAP,NP,large: DigiKey: 1276-2117-1-ND; DigiReel: 1276-2117-6-ND; Family: passive; Lead Style: SMT; MFG: Samsung; Material: x7r; P/D_NUM: CL10B821KB8NNNC; Part Number: CL10B821KB8NNNC; Part Specific: CAP CER 820PF 50V 10% X7R 0603; TOLERANCE: 10%; Type: capacitor; VENDOR: Samsung; VPC: 50V; Voltage: 50V
C14 C15 C17 = PAS,CAP,NP,large: DigiKey: 445-14696-1-ND; DigiReel: 445-14696-6-ND; Family: passive; Lead Style: SMT; MFG: TDK; Material: x5r; P/D_NUM: C3216X5R1V156M160AC; Part Number: C3216X5R1V156M160AC; Part Specific: CAP CER 15UF 35V 20% X5R 1206; TOLERANCE: 20%; Type: capacitor; VENDOR: TDK; VPC: 35V; Voltage: 35V
C16 = CAP_POL_dsize_0: DigiKey: PCE5016CT-ND; DigiReel: PCE5016DKR-ND; Family: passive; Install: Y; Lead Style: SMT; MFG: Panasonic; P/D_NUM: EEE-FT1V101AP; Part Number: EEE-FT1V101AP; Part Specific: CAP ALUM 100UF 20% 35V SMD; RATING/TOLERANCE: 20%; Tolerance: 20%; Type: capacitor; VPC: 35V; Vendor: Panasonic; Voltage: 35V
C18 = PAS,CAP,NP,large: DigiKey: 399-1280-1-ND; DigiReel: 399-1280-6-ND; Family: passive; Lead Style: SMT; MFG: AVX; Material: x7r; P/D_NUM: C0603C223K5RACTU; Part Number: C0603C223K5RACTU; Part Specific: CAP CER 0.022UF 50V 10% X7R 0603; TOLERANCE: 10%; Type: capacitor; VENDOR: AVX; VPC: 50V
C23 = PAS,CAP,NP,large: DigiKey: 1276-1860-1-ND; DigiReel: 1276-1860-6-ND; Family: passive; Lead Style: SMT; MFG: Samsung; Material: X5R; P/D_NUM: CL10A105KB8NNNC; Part Number: CL10A105KB8NNNC; Part Specific: CAP CER 1UF 50V 10% X5R 0603; TOLERANCE: 10%; Type: capacitor; VENDOR: Samsung; VPC: 50V; Voltage: 50V
C25 = PAS,CAP,NP,large: DigiKey: 1276-1188-1-ND; DigiReel: 1276-1188-6-ND; Family: passive; Lead Style: SMT; MFG: Samsung; Material: x7r; P/D_NUM: CL21B225KPFNNNE; Part Number: CL21B225KPFNNNE; Part Specific: CAP CER 2.2UF 10V 10% X7R 0805; TOLERANCE: 10%; Type: capacitor; VENDOR: TDK; VPC: 10V; Voltage: 10V
C26 C30 = PAS,CAP,NP,large: DigiKey: 1276-2409-1-ND; DigiReel: 1276-2409-6-ND; Family: passive; Lead Style: SMT; MFG: Samsung; Material: x5r; P/D_NUM: CL21A225KB9LNNC; Part Number: CL21A225KB9LNNC; Part Specific: CAP CER 2.2UF 50V 10% X5R 0805; TOLERANCE: 10%; Type: capacitor; VENDOR: Samsung; VPC: 50V
C27 = PAS,CAP,NP,large: DigiKey: 1276-1860-1-ND; DigiReel: 1276-1860-6-ND; Family: passive; Lead Style: SMT; MFG: Samsung; Material: x5r; P/D_NUM: CL10A105KB8NNNC; Part Number: CL10A105KB8NNNC; Part Specific: CAP CER 1UF 50V 10% X5R 0603; TOLERANCE: 10%; Type: capacitor; VENDOR: Samsung; VPC: 50V
C28 C527 = PAS,CAP,NP,large: DigiKey: 478-1395-1-ND; DigiReel: 478-1395-6-ND; Family: passive; Lead Style: SMT; MFG: AVX; Material: x7r; P/D_NUM: 08055C104KAT2A; Part Number: 08055C104KAT2A; Part Specific: CAP CER 0.1UF 50V 10% X7R 0805; TOLERANCE: 10%; Type: capacitor; VENDOR: AVX; VPC: 50V
C29 = PAS,CAP,NP,large: DigiKey: 490-5402-1-ND; DigiReel: 490-5402-6-ND; Family: passive; Lead Style: SMT; MFG: Murata; Material: x7r; P/D_NUM: GCM188R71H224KA64D; Part Number: GCM188R71H224KA64D; Part Specific: CAP CER 0.22UF 50V 10% X7R 0805; TOLERANCE: 10%; Type: capacitor; VENDOR: Murata; VPC: 50V
C31 = PAS,CAP,NP,large: DigiKey: 1276-2620-1-ND; DigiReel: 1276-2620-6-ND; Family: passive; Lead Style: SMT; MFG: Samsung; Material: np0; P/D_NUM: CL21C241JBANNNC; Part Number: CL21C241JBANNNC; Part Specific: CAP CER 240PF 50V 5% C0G/NP0 0805; TOLERANCE: 5%; Type: capacitor; VENDOR: Samsung; VPC: 50V; Voltage: 50V
C32 = PAS,CAP,NP,large: DigiKey: 1276-1177-1-ND; DigiReel: 1276-1177-6-ND; Family: passive; Lead Style: SMT; MFG: Samsung; Material: x7r; P/D_NUM: CL05B333KO5NNNC; Part Number: CL05B333KO5NNNC; Part Specific: CAP CER 0.033UF 16V 10% X7R 0402; TOLERANCE: 10%; Type: capacitor; VENDOR: Samsung; VPC: 16V; Voltage: 16V
C504 = PAS,CAP,NP,large: DigiKey: 490-10956-1-ND; DigiReel: 490-10956-6-ND; Family: passive; Index PN: 1601; Lead Style: SMT; MFG: Murata; Material: x7s; P/D_NUM: GRJ32EC71H106KE11L; Part Number: GRJ32EC71H106KE11L; Part Specific: CAP CER 10UF 50V 10% X7S 1210; TOLERANCE: 10%; Type: capacitor; VENDOR: Murata; VPC: 50V; Voltage: 50V
C510 = PAS,CAP,NP,large: DigiKey: 1276-2690-1-ND; DigiReel: 1276-2690-6-ND; Family: passive; Lead Style: SMT; MFG: Samsung; Material: np0; P/D_NUM: CL21C750JBANNNC; Part Number: CL21C750JBANNNC; Part Specific: CAP CER 75PF 50V 5% C0G/NP0 0805; TOLERANCE: 5%; Type: capacitor; VENDOR: Samsung; VPC: 50V; Voltage: 50V
C511 C517 = PAS,CAP,NP,large: DigiKey: 490-5318-1-ND; DigiReel: 490-5318-6-ND; Family: passive; Lead Style: SMT; MFG: Murata; Material: np0; P/D_NUM: GCM21B5C1H223JA16L; Part Number: GCM21B5C1H223JA16L; Part Specific: CAP CER 0.022UF 50V 5% C0G/NP0 0805; TOLERANCE: 5%; Type: capacitor; VENDOR: Murata; VPC: 50V
C516 = PAS,CAP,NP,large: DigiKey: 490-1452-1-ND; DigiReel: 490-1452-6-ND; Family: passive; Lead Style: SMT; MFG: Murata; Material: np0; P/D_NUM: GRM1885C1H112JA01D; Part Number: GRM1885C1H112JA01D; Part Specific: CAP CER 1100PF 50V 5% C0G/NP0 0603; TOLERANCE: 5%; Type: capacitor; VENDOR: Murata; VPC: 50V; Voltage: 50V
D1 = PAS,DIODE,LED,large: DigiKey: 67-1701-1-ND; DigiReel: 67-1701-6-ND; Family: passive; Install: Y; Lead Style: SMT; MFG: Lumex; P/D_NUM: SML-LX1206USBC-TR; Part Number: SML-LX1206USBC-TR; Part Specific: LED INGAN/SIC U-BLUE CLR 1206 SMD; Type: diode,led; VENDOR: Lumex
D2 = PAS,DIODE,SCHOTTKY,large: DigiKey: B560C-FDICT-ND; DigiReel: B560C-FDIDKR-ND; Family: passive; Lead Style: SMT; MFG: Diodes Inc; P/D_NUM: B560C-13-F; Part Number: B560C-13-F; Part Specific: DIODE SCHOTTKY 60V 5A SMC; Type: diode,schottky; VENDOR: Diodes Inc; VPC: 5A; Voltage: 60V
D3 = PAS,DIODE,SCHOTTKY,DPAK,small: DigiKey: VS-50WQ10FNTRL-M3GICT-ND; DigiReel: VS-50WQ10FNTRL-M3GIDKR-ND; Lead Style: SMT; MFG: Vishay; P/D_NUM: VS-50WQ10FNTRL-M3; Part Number: VS-50WQ10FNTRL-M3; Part Specific: DIODE SCHOTTKY 100V 5.5A DPAK; VENDOR: Vishay; VPC: 5.5A; Voltage: 100V
FB1 = PAS,FERRITE_BEAD,3: DigiKey: 240-2521-1-ND; DigiReel: 240-2521-6-ND; Family: passive; Install: Y; Lead Style: SMT; MFG: Laird; Part Specific: FERRITE BEAD 82 OHM 10A 2SMD 1LN; Type: ferrite bead; VENDOR: Laird; VPC: 10A
L1 = PAS,INDUCTOR,_large: DigiKey: SRP5030T-5R6MCT-ND; DigiReel: SRP5030T-5R6MDKR-ND; Family: passive; Lead Style: SMT; MFG: Bourns; P/D_NUM: SRP5030T-5R6M; Part Number: SRP5030T-5R6M; Part Specific: FIXED IND 5.6UH 4.25A 63 MOHM SMD; Type: inductor; VENDOR: Bourns; VPC: 4.25A
L2 = PAS,INDUCTOR,_large: DigiKey: ---; DigiReel: ---; Family: passive; Lead Style: SMT; MFG: Coilcraft; P/D_NUM: XAL7030-562MEB; Part Number: XAL7030-562MEB; Part Specific: INDUCTOR 5.6UH 7.3A 32.32MOHM 20% SMD; Tolerance: 20%; Type: inductor; VENDOR: Coilcraft; VPC: 7.3A
Q1 = ANA,MOSFET,P-CH,E,SOT223_2: DigiKey: NDT456PCT-ND; DigiReel: NDT456PDKR-ND; Family: analog; Lead Style: SMT; MFG: ON Semi; Part Specific: MOSFET P-CH 30V 7.5A SOT-223-4; Type: fet; VPC: 30V; Vendor: ON Semi
Q2 = ANA,MOSFET,N-CH,E,2N7002,SOT-23: DigiKey: RK7002BMT116CT-ND; DigiReel: RK7002BMT116DKR-ND; Digikey Part Number: RK7002BMT116CT-ND; Family: analog; Lead Style: SMT; MFG: Rohm; P/D_NUM: RK7002BMT116; Part Number: RK7002BMT116; Part Specific: MOSFET N-CH 60V 250MA SOT23-3; Type: fet; VPC: 60V; Vendor: Rohm
Q3 = ANA,FET,TI_NexFET_8SON: DigiKey: 296-47321-1-ND; DigiReel: 296-47321-6-ND; Family: analog; Install: Y; Lead Style: SMT; MFG: Texas Instruments; Part Specific: MOSFET N-CH 60V 35A 8SON; Type: MOSFET; VENDOR: Texas Instruments; VPC: 35A; Voltage: 60V
R6 = PAS,R,large: DigiKey: P665CCT-ND; DigiReel: P665CDKR-ND; Family: passive; Lead Style: SMT; MFG: Panasonic; Material: chip; P/D_NUM: ERJ-6ENF6650V; Part Number: ERJ-6ENF6650V; Part Specific: RES 665 OHM 1% 1/8W 0805 SMD; TOLERANCE: 1%; Type: resistor; VENDOR: Panasonic; VPC: 1/8W
R7 = PAS,R,large: DigiKey: P147KLCT-ND; DigiReel: P147KLDKR-ND; Family: passive; Lead Style: SMT; MFG: Panasonic; Material: chip; P/D_NUM: ERJ-2RKF1473X; Part Number: ERJ-2RKF1473X; Part Specific: RES 147K OHM 1% 1/10W 0402 SMD; Tolerance: 1%; Type: resistor; VPC: 1/10W; Vendor: Panasonic
R8 = PAS,R,large: DigiKey: P10.5KLCT-ND; DigiReel: P10.5KLDKR-ND; Family: passive; Lead Style: SMT; MFG: Panasonic; P/D_NUM: ERJ-2RKF1052X; Part Number: ERJ-2RKF1052X; Part Specific: RES SMD 10.5K OHM 1% 1/10W 0402; Tolerance: 1%; Type: resistor; Vendor: Panasonic
R9 = PAS,R,large: DigiKey: P56.2KLCT-ND; DigiReel: P56.2KLDKR-ND; Family: passive; Lead Style: SMT; MFG: Panasonic; Material: chip; P/D_NUM: ERJ-2RKF5622X; Part Number: ERJ-2RKF5622X; Part Specific: RES 56.2K OHM 1% 1/10W 0402 SMD; Tolerance: 1%; Type: resistor; VPC: 1/10W; Vendor: Panasonic
R10 = PAS,R,large: DigiKey: 541-93.1KLCT-ND; DigiReel: 541-93.1KLDKR-ND; Family: passive; Lead Style: SMT; MFG: Vishay/Dale; Material: chip; P/D_NUM: CRCW040293K1FKED; Part Number: CRCW040293K1FKED; Part Specific: RES SMD 93.1K OHM 1% 1/16W 0402; Tolerance: 1%; Type: resistor; VPC: 1/16W; Vendor: Vishay/Dale
R11 R36 = PAS,R,large: DigiKey: P0.0JCT-ND; DigiReel: P0.0JDKR-ND; Family: passive; Index PN: 687; Install: DNI; Lead Style: SMT; MFG: Panasonic; Material: chip; P/D_NUM: ERJ-2GE0R00X; Part Number: ERJ-2GE0R00X; Part Specific: RES 0.0 OHM 1/16W 0402 SMD; Power: 1/16W; Type: resistor; VPC: 1/16W; Vendor: Panasonic
R12 = PAS,R,large: DigiKey: 541-0.0VCT-ND; DigiReel: 541-0.0VCDKR-ND; Family: passive; Install: DNI; Lead Style: SMT; MFG: Vishay; Material: chip; P/D_NUM: CRCW12100000Z0EA; Part Number: CRCW12100000Z0EA; Part Specific: RES 0.0 OHM 5A JUMP 1210 SMD; Power: 1/2W; Type: resistor; VENDOR: Vishay; VPC: 5A
R13-R15 R26 = PAS,R,large: DigiKey: P10.0KHCT-ND; DigiReel: P10.0KHDKR-ND; Family: passive; Lead Style: SMT; MFG: Panasonic; Material: chip; P/D_NUM: ERJ-3EKF1002V; Part Number: ERJ-3EKF1002V; Part Specific: RES 10K OHM 1% 1/10W 0603 SMD; Tolerance: 1%; Type: resistor; VPC: 1/10W; Vendor: Panasonic
R16 = PAS,R,large: DigiKey: P1.00KLCT-ND; DigiReel: P1.00KLDKR-ND; Family: passive; Index PN: 684; Install: Y; Lead Style: SMT; MFG: Panasonic; Material: chip; P/D_NUM: ERJ-2RKF1001X; Part Number: ERJ-2RKF1001X; Part Specific: RES 1.00K OHM 1/10W 1% 0402 SMD; Power: 1/16W; TOLERANCE: 1%; Type: resistor; VENDOR: Panasonic; VPC: 1/16W
R17 = PAS,R,large: DigiKey: P1.00KLCT-ND; DigiReel: P1.00KLDKR-ND; Family: passive; Index PN: 684; Install: DNI; Lead Style: SMT; MFG: Panasonic; Material: chip; P/D_NUM: ERJ-2RKF1001X; Part Number: ERJ-2RKF1001X; Part Specific: RES 1.00K OHM 1/10W 1% 0402 SMD; Power: 1/16W; TOLERANCE: 1%; Type: resistor; VENDOR: Panasonic; VPC: 1/16W
R24 = PAS,R,large: DigiKey: P3.00BZCT-ND; DigiReel: P3.00BZDKR-ND; Family: passive; Lead Style: SMT; MFG: Panasonic; Material: chip; P/D_NUM: ERJ-PA3J3R0V; Part Number: ERJ-PA3J3R0V; Part Specific: RES 3 OHM 5% 1/4W 0603 SMD; Power: 1/4W; Tolerance: 5%; Type: resistor; VPC: 1/4W; Vendor: Panasonic
R25 = PAS,R,large: DigiKey: P1.65KLCT-ND; DigiReel: P1.65KLDKR-ND; Family: passive; Lead Style: SMT; MFG: Panasonic; Material: chip; P/D_NUM: ERJ-2RKF1651X; Part Number: ERJ-2RKF1651X; Part Specific: RES 1.65K OHM 1% 1/10W 0402 SMD; Tolerance: 1%; Type: resistor; VPC: 1/10W; Vendor: Panasonic
R34 = PAS,R,large: DigiKey: P0.011BVCT-ND; DigiReel: P0.011BVCT-ND; Family: passive; Lead Style: SMT; MFG: Panasonic; Material: chip; P/D_NUM: ERJ-8CWFR011V; Part Number: ERJ-8CWFR011V; Part Specific: RES 0.011 OHM 1% 1W 1206 SMD; Power: 1W; Tolerance: 1%; Type: resistor; VPC: 1W; Vendor: Rohm
R35 = PAS,R,large: DigiKey: RT0805BRD07223KL-ND; DigiReel: RT0805BRD07223KL-ND; Family: passive; Lead Style: SMT; MFG: Yageo; Material: chip; P/D_NUM: RT0805BRD07223KL; Part Number: RT0805BRD07223KL; Part Specific: RES 223K OHM 0.1% 1/8W 0805 SMD; Power: 1/8W; Tolerance: 0.1%; Type: resistor; VPC: 1/8W; Vendor: Yageo
R519 = PAS,R,large: DigiKey: P19.6KCCT-ND; DigiReel: P19.6KCDKR-ND; Family: passive; Lead Style: SMT; MFG: Panasonic; Material: chip; P/D_NUM: ERJ-6ENF1962V; Part Number: ERJ-6ENF1962V; Part Specific: RES 19.6K OHM 1% 1/8W 0805 SMD; Tolerance: 1%; Type: resistor; VPC: 1/8W; Vendor: Panasonic
R520 = PAS,R,large: DigiKey: P14.7KLCT-ND; DigiReel: P14.7KLDKR-ND; Family: passive; Lead Style: SMT; MFG: Panasonic; Material: chip; P/D_NUM: ERJ-2RKF1472X; Part Number: ERJ-2RKF1472X; Part Specific: RES 14.7K OHM 1% 1/10W 0402 SMD; Tolerance: 1%; Type: resistor; VPC: 1/10W; Vendor: Panasonic
U4 = PWR,REG,TPS54340,HSOIC,DDA: DigiKey: 296-35072-1-ND; DigiReel: 296-35072-6-ND; Family: power; Index PN: 1264; Install: Y; Lead Style: SMT; MFG: Texas Instruments; P/D_NUM: TPS54340DDAR; Part Number: TPS54340DDAR; Part Specific: IC REG BUCK ADJ 3.5A 8SOPWRPAD; Type: regulator; Vendor: Texas Instruments
U5 = LOG,BUF,SCHMITT,SN74AUP1T17DCK: DigiKey: 296-27395-1-ND; DigiReel: 296-27395-6-ND; Family: logic; Index PN: 1199; Lead Style: SMT; MFG: Texas Instruments; P/D_NUM: SN74AUP1T17DCKR; Part Number: SN74AUP1T17DCKR; Part Specific: IC BUFFER SCHMITT TRIG LP SC70-5; Type: buffer
U13 = PWR,REG,LP2980,SOT23_DBV_0: DigiKey: LP2980IM5-3.3/NOPBCT-ND; DigiReel: LP2980IM5-3.3/NOPBDKR-ND; Install: Y; Lead Style: SMT; MFG: Texas Instruments; P/D_NUM: LP2980IM5-3.3/NOPBCT-ND; Part Number: LP2980IM5-3.3/NOPBCT-ND; Part Specific: IC REG LINEAR 3.3V 50MA SOT23-5; Type: regulator; Vendor: Texas Instruments
U14 = PWR,CNTRL,LM25088,TSSOP16_PWP_0: DigiKey: 296-43294-1-ND; DigiReel: 296-43294-6-ND; Install: Y; Lead Style: SMT; MFG: Texas Instruments; P/D_NUM: LM25088MHX-2/NOPB; Part Number: LM25088MHX-2/NOPB; Part Specific: IC REG CTRLR BUCK 16TSSOP; Pin Cnt: 16; Type: buck controller; VENDOR: Texas Instruments

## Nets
DGND: C3.2(N) C4.2(N) C6.2(N) C7.2(N) C11.2(N) C12.2(N) C14.1(P) C15.1(P) C16.1 C17.1(P) C23.2(N) C25.2(N) C26.2(N) C30.1(P) C37.2(N) C504.2(N) C511.1(P) C517.1(P) C527.1(P) C537.2(N) C538.2(N) C539.2(N) C540.2(N) C541.2(N) C542.2(N) C543.2(N) C544.2(N) C545.2(N) C546.2(N) C547.2(N) C553.2(N) C554.2(N) C555.2(N) C556.2(N) C557.2(N) C558.2(N) C559.2(N) C560.2(N) C587.2(N) C680.2(N) C681.2(N) D1.1(P1) D2.2(P2) J13.29(P29) J13.32(P32) J13.35(P35) J13.38(P38) J13.41(P41) J13.44(P44) J13.47(P47) J13.50(P50) J13.53(P53) J13.56(P56) J13.59(P59) J13.G1 J13.G2 J13.G3 J13.G4 L2.1 Q2.2(SOURCE) R8.2(N2) R10.2(N2) R40.1(N1) R42.2(N2) R64.1(N1) R91.1(N1) R507.2(N2) R520.1(N1) R578.2(N2) R579.2(N2) R594.2(N2) R601.1(N1) R618.1(N1) U4.7(GND) U4.9(PAD) U5.3(GND) U13.2(GND) U14.9(OUT) U20.A9(Vss) U20.B1(VssQ) U20.B3(Vss) U20.B9(VssQ) U20.D1(VssQ) U20.D8(VssQ) U20.E1(Vss) U20.E2(VssQ) U20.E8(VssQ) U20.F9(VssQ) U20.G1(VssQ) U20.G8(Vss) U20.G9(VssQ) U20.J2(Vss) U20.J8(Vss) U20.M1(Vss) U20.M9(Vss) U20.P1(Vss) U20.P9(Vss) U20.T1(Vss) U20.T9(Vss) U33.4(GND) U35.C10(HWTEST_EN) U36.3(GND) U41.2(GND) ; also on sheet 1 2 4 7 8 9 10 16 17
P5V: C23.1(P) R41.1(N1) U13.1(VIN) ; also on sheet 2 8 9
P12V: C11.1(P) C12.1(P) L1.1 R6.2(N2) R7.2(N2) ; also on sheet 2 10
P12V_BOOT: C5.2(N) U4.1(BOOT)
P12V_COMP: C4.1(P) R9.1(N1) U4.6(COMP)
P12V_EN: R11.2(N2) U4.3(EN)
P12V_FB: R7.1(N1) R8.1(N1) U4.5(FB)
P12V_LED: D1.2(P2) R6.1(N1)
P12V_RC_1: C3.1(P) R9.2(N2)
P12V_RT: R10.1(N1) U4.4(RT/CLK)
P12V_SW: C5.1(P) D2.1(P1) L1.2 U4.8(SW)
P19V: Q1.S(SOURCE) R12.2(N2) R13.1(N1) ; also on sheet 8 9
P19V_ACT: C6.1(P) C7.1(P) C27.2(N) C30.2(N) C504.1(P) C527.2(N) Q1.D1(DRAIN1) Q1.D2(DRAIN2) Q3.5(D4) Q3.6(D3) Q3.7(D2) Q3.8(D1) R12.1(N1) U4.2(VIN) U14.1(VIN)
P19V_QG: Q1.G(GATE) R13.2(N2) R14.1(N1)
VCCDDR: C38.1(P) C538.1(P) C540.1(P) C541.1(P) C542.1(P) C543.1(P) C544.1(P) C546.1(P) C553.1(P) C555.1(P) C556.1(P) C559.1(P) C560.1(P) R43.1(N1) R567.1(N1) U20.A1(VddQ) U20.A8(VddQ) U20.B2(Vdd) U20.C1(VddQ) U20.C9(VddQ) U20.D2(VddQ) U20.D9(Vdd) U20.E9(VddQ) U20.F1(VddQ) U20.G7(Vdd) U20.H2(VddQ) U20.H9(VddQ) U20.K2(Vdd) U20.K8(Vdd) U20.N1(Vdd) U20.N9(Vdd) U20.R1(Vdd) U20.R9(Vdd) ; also on sheet 2
DAC_EN_G: Q2.1(GATE) R15.2(N2)
DAC_ENAB: R11.1(N1) R15.1(N1) R507.1(N1) U5.2(A) ; also on sheet 16
DAC_ENAB_B: R16.1(N1) U5.4(Y)
DAC_VREF: C25.1(P) U13.5(SW) ; also on sheet 10
DDR_A0: R560.1(N1) U20.N3(A00)
DDR_A1: R558.1(N1) U20.P7(A01)
DDR_A2: R556.1(N1) U20.P3(A02)
DDR_A3: R557.1(N1) U20.N2(A03)
DDR_A4: R550.1(N1) U20.P8(A04)
DDR_A5: R554.1(N1) U20.P2(A05)
DDR_A6: R544.1(N1) U20.R8(A06)
DDR_A7: R553.1(N1) U20.R2(A07)
DDR_A8: R545.1(N1) U20.T8(A08)
DDR_A9: R549.1(N1) U20.R3(A09)
DDR_A10: R555.1(N1) U20.L7(A10/AP)
DDR_A11: R546.1(N1) U20.R7(A11)
DDR_A12: R547.1(N1) U20.N7(A12/BC#)
DDR_BA0: R559.1(N1) U20.M2(BA0)
DDR_BA1: R552.1(N1) U20.N8(BA1)
DDR_BA2: R561.1(N1) U20.M3(BA2)
DDR_CAS_B: R564.1(N1) U20.K3(~{CAS})
DDR_CKE: R72.1(N1) U20.K9(CKE)
DDR_CKN: R534.1(N1) U20.K7(~{CK}) U26.N5(PS_DDR_CKN_502)
DDR_CKP: R534.2(N2) U20.J7(CK) U26.N4(PS_DDR_CKP_502)
DDR_CS_B: R562.1(N1) U20.L2(~{CS})
DDR_DM0: R73.1(N1) U20.E7(LDM)
DDR_DM1: R551.1(N1) U20.D3(UDM)
DDR_DQ0: U20.E3(DQ0) U26.D1(PS_DDR_DQ0_502)
DDR_DQ1: U20.F7(DQ1) U26.C3(PS_DDR_DQ1_502)
DDR_DQ2: U20.F2(DQ2) U26.B2(PS_DDR_DQ2_502)
DDR_DQ3: U20.F8(DQ3) U26.D3(PS_DDR_DQ3_502)
DDR_DQ4: U20.H3(DQ4) U26.E3(PS_DDR_DQ4_502)
DDR_DQ5: U20.H8(DQ5) U26.E1(PS_DDR_DQ5_502)
DDR_DQ6: U20.G2(DQ6) U26.F2(PS_DDR_DQ6_502)
DDR_DQ7: U20.H7(DQ7) U26.F1(PS_DDR_DQ7_502)
DDR_DQ8: U20.D7(DQ8) U26.G2(PS_DDR_DQ8_502)
DDR_DQ9: U20.C3(DQ9) U26.G1(PS_DDR_DQ9_502)
DDR_DQ10: U20.C8(DQ10) U26.L1(PS_DDR_DQ10_502)
DDR_DQ11: U20.C2(DQ11) U26.L2(PS_DDR_DQ11_502)
DDR_DQ12: U20.A7(DQ12) U26.L3(PS_DDR_DQ12_502)
DDR_DQ13: U20.A2(DQ13) U26.K1(PS_DDR_DQ13_502)
DDR_DQ14: U20.B8(DQ14) U26.J1(PS_DDR_DQ14_502)
DDR_DQ15: U20.A3(DQ15) U26.K3(PS_DDR_DQ15_502)
DDR_DQS_N0: R537.2(N2) U20.G3(~{LDQS}) U26.D2(PS_DDR_DQS_N0_502)
DDR_DQS_N1: R535.2(N2) U20.B7(~{UDQS}) U26.J2(PS_DDR_DQS_N1_502)
DDR_DQS_P0: R537.1(N1) U20.F3(LDQS) U26.C2(PS_DDR_DQS_P0_502)
DDR_DQS_P1: R535.1(N1) U20.C7(UDQS) U26.H2(PS_DDR_DQS_P1_502)
DDR_DRST_B: R64.2(N2) R548.1(N1) U20.T2(~{RESET})
DDR_ODT: R563.1(N1) U20.K1(ODT)
DDR_RAS_B: R566.1(N1) U20.J3(~{RAS})
DDR_T_A0: R560.2(N2) U26.M4(PS_DDR_A0_502)
DDR_T_A1: R558.2(N2) U26.M5(PS_DDR_A1_502)
DDR_T_A2: R556.2(N2) U26.K4(PS_DDR_A2_502)
DDR_T_A3: R557.2(N2) U26.L4(PS_DDR_A3_502)
DDR_T_A4: R550.2(N2) U26.K6(PS_DDR_A4_502)
DDR_T_A5: R554.2(N2) U26.K5(PS_DDR_A5_502)
DDR_T_A6: R544.2(N2) U26.J7(PS_DDR_A6_502)
DDR_T_A7: R553.2(N2) U26.J6(PS_DDR_A7_502)
DDR_T_A8: R545.2(N2) U26.J5(PS_DDR_A8_502)
DDR_T_A9: R549.2(N2) U26.H5(PS_DDR_A9_502)
DDR_T_A10: R555.2(N2) U26.J3(PS_DDR_A10_502)
DDR_T_A11: R546.2(N2) U26.G5(PS_DDR_A11_502)
DDR_T_A12: R547.2(N2) U26.H4(PS_DDR_A12_502)
DDR_T_BA0: R559.2(N2) U26.L7(PS_DDR_BA0_502)
DDR_T_BA1: R552.2(N2) U26.L6(PS_DDR_BA1_502)
DDR_T_BA2: R561.2(N2) U26.M6(PS_DDR_BA2_502)
DDR_T_CAS_B: R564.2(N2) U26.P3(PS_DDR_CAS_B_502)
DDR_T_CKE: R72.2(N2) U26.V3(PS_DDR_CKE_502)
DDR_T_CS_B: R562.2(N2) U26.P6(PS_DDR_CS_B_502)
DDR_T_DM0: R73.2(N2) U26.B1(PS_DDR_DM0_502)
DDR_T_DM1: R551.2(N2) U26.H3(PS_DDR_DM1_502)
DDR_T_DRST_B: R548.2(N2) U26.F3(PS_DDR_DRST_B_502)
DDR_T_ODT: R563.2(N2) U26.P5(PS_DDR_ODT_502)
DDR_T_RAS_B: R566.2(N2) U26.R5(PS_DDR_RAS_B_502)
DDR_T_WE_B: R565.2(N2) U26.R4(PS_DDR_WE_B_502)
DDR_VREF: C37.1(P) C38.2(N) C537.1(P) C539.1(P) C545.1(P) C547.1(P) C554.1(P) C557.1(P) C558.1(P) C587.1(P) R42.1(N1) R43.2(N2) U20.H1(VREFDQ) U20.M8(VREFCA) U26.H7(PS_DDR_VREF0_502) U26.P7(PS_DDR_VREF1_502)
DDR_VRN: R567.2(N2) U26.M7(PS_DDR_VRN_502)
DDR_VRP: R594.1(N1) U26.N7(PS_DDR_VRP_502)
DDR_WE_B: R565.1(N1) U20.L3(~{WE})
DDR_ZQ: R40.2(N2) U20.L8(ZQ)
DLPC_SPICLK: R83.2(N2) U35.A13(SPI0_CLK)
DLPC_SPICSZ0: R86.2(N2) U35.A14(SPI0_CSZ0)
DLPC_SPIDOUT: R82.2(N2) U35.B13(SPI0_DOUT)
FLSH_MISO: R576.1(N1) U33.2(DO)
FPD0_An: J13.60(P60) R615.1(N1) U26.A22(IO_L15N_T2_DQS_AD12N_35)
FPD0_Ap: J13.58(P58) R615.2(N2) U26.A21(IO_L15P_T2_DQS_AD12P_35)
FPD0_Bn: J13.57(P57) R627.1(N1) U26.A19(IO_L10N_T1_AD11N_35)
FPD0_Bp: J13.55(P55) R627.2(N2) U26.A18(IO_L10P_T1_AD11P_35)
FPD0_CLKn: J13.54(P54) R614.1(N1) U26.B20(IO_L13N_T2_MRCC_35)
FPD0_CLKp: J13.52(P52) R614.2(N2) U26.B19(IO_L13P_T2_MRCC_35)
FPD0_Cn: J13.51(P51) R626.1(N1) U26.A17(IO_L9N_T1_DQS_AD3N_35)
FPD0_Cp: J13.49(P49) R626.2(N2) U26.A16(IO_L9P_T1_DQS_AD3P_35)
FPD0_Dn: J13.48(P48) R613.1(N1) U26.B22(IO_L18N_T2_AD13N_35)
FPD0_Dp: J13.46(P46) R613.2(N2) U26.B21(IO_L18P_T2_AD13P_35)
FPD0_En: J13.30(P30) R610.1(N1) U26.B17(IO_L8N_T1_AD10N_35)
FPD0_Ep: J13.28(P28) R610.2(N2) U26.B16(IO_L8P_T1_AD10P_35)
FPD1_An: J13.45(P45) R625.1(N1) U26.C22(IO_L16N_T2_35)
FPD1_Ap: J13.43(P43) R625.2(N2) U26.D22(IO_L16P_T2_35)
FPD1_Bn: J13.42(P42) R612.1(N1) U26.D21(IO_L17N_T2_AD5N_35)
FPD1_Bp: J13.40(P40) R612.2(N2) U26.E21(IO_L17P_T2_AD5P_35)
FPD1_CLKn: J13.39(P39) R624.1(N1) U26.C19(IO_L12N_T1_MRCC_35)
FPD1_CLKp: J13.37(P37) R624.2(N2) U26.D18(IO_L12P_T1_MRCC_35)
FPD1_Cn: J13.36(P36) R611.1(N1) U26.C20(IO_L14N_T2_AD4N_SRCC_35)
FPD1_Cp: J13.34(P34) R611.2(N2) U26.D20(IO_L14P_T2_AD4P_SRCC_35)
FPD1_Dn: J13.33(P33) R623.1(N1) U26.E20(IO_L21N_T3_DQS_AD14N_35)
FPD1_Dp: J13.31(P31) R623.2(N2) U26.E19(IO_L21P_T3_DQS_AD14P_35)
FPD1_En: J13.27(P27) R622.1(N1) U26.D17(IO_L2N_T0_AD8N_35)
FPD1_Ep: J13.25(P25) R622.2(N2) U26.D16(IO_L2P_T0_AD8P_35)
FPGA_RESETZ: R602.1(N1) TP37.1(P1) U26.Y18(IO_L12P_T1_MRCC_33) ; also on sheet 4
HOST_IRQ: R621.2(N2) TP35.1(P1) U35.N8(HOST_IRQ) U36.2(A) ; also on sheet 9
I2C0_SCL: TP48.1(P1) U35.N10(IIC0_SCL) ; also on sheet 9
I2C0_SDA: TP47.1(P1) U35.N9(IIC0_SDA) ; also on sheet 9
I2C1_SCL: R92.2(N2) TP38.1(P1) U26.AB14(IO_L24P_T3_33) U35.R11(IIC1_SCL)
I2C1_SDA: R93.2(N2) TP39.1(P1) U26.AB15(IO_L24N_T3_33) U35.R10(IIC1_SDA)
INTZ: TP29.1(P1) U35.C13(PARKZ) ; also on sheet 2 8
JTAG_TRSTZ: R91.2(N2) U35.P11(JTAGTRSTZ)
N12_BOOT: C28.2(N) U14.15(BOOT)
N12_COMP: C510.2(N) R519.2(N2) U14.7(COMP)
N12_CS: C13.1(P) D3.1(P1) D3.3(P3) R34.2(N2) U14.12(CS)
N12_EN: R36.2(N2) U14.2(EN)
N12_ENAB: R16.2(N2) R17.1(N1) R36.1(N1)
N12_FB: C510.1(P) C516.1(P) R25.1(N1) R520.2(N2) U14.8(FB)
N12_HG: Q3.4(G) U14.14(HG)
N12_L: C28.1(P) D3.4(P4) L2.2 Q3.1(S1) Q3.2(S2) Q3.3(S3) R24.2(N2) U14.13(SW)
N12_OUT: C14.2(N) C15.2(N) C17.2(N) C18.1(P) C26.1(P) C27.1(P) C29.1(P) C31.2(N) C32.2(N) C517.2(N) FB1.1(N1) R17.2(N2) R25.2(N2) R26.2(N2) R34.1(N1) U14.6(GND) U14.11(CSG) U14.17(GND_PAD)
N12_RAMP: C31.1(P) R35.1(N1) U14.4(RAMP)
N12_RC1: C516.2(N) R519.1(N1)
N12_RES: C18.2(N) U14.10(DITH/RES)
N12_RT: R26.1(N1) U14.5(RT/SYNC)
N12_SS: C32.1(P) U14.3(SS)
N12_VCC: C29.2(N) R35.2(N2) U14.16(VCC)
N12V: C16.2 C511.2(N) FB1.2(N2) ; also on sheet 10
OSC_OUT: R90.2(N2) U35.H1(PLL_REFCLK_I)
OSC_OUT_T: R90.1(N1) U41.3(OUT)
P1P8V: R602.2(N2) ; also on sheet 2 16 17
P1P8V_DLPA: C680.1(P) C681.1(P) R92.1(N1) R93.1(N1) R621.1(N1) U36.5(PWR) U41.1(EN) U41.4(VDD) ; also on sheet 1 2 4 7 8
P2P5V_DLPA: D7.2(P2) ; also on sheet 2 8
P3P3V: U5.5(PWR) ; also on sheet 2 10 16
P3P3V_SB: R577.1(N1) U33.3(~{WP}) U33.7(~{HOLD}) U33.8(VCC3) ; also on sheet 2 7 9 17
PDAT_0: U26.T22(IO_L2P_T0_33) U35.K2(PDATA_0)
PDAT_1: U26.V22(IO_L3P_T0_DQS_33) U35.K1(PDATA_1)
PDAT_2: U26.W22(IO_L3N_T0_DQS_33) U35.L2(PDATA_2)
PDAT_3: U26.AA22(IO_L7P_T1_33) U35.L1(PDATA_3)
PDAT_3DR: R618.2(N2) U26.U22(IO_L2N_T0_33) U35.N6(3DR)
PDAT_4: U26.AB22(IO_L7N_T1_33) U35.M2(PDATA_4)
PDAT_5: U26.T21(IO_L1P_T0_33) U35.M1(PDATA_5)
PDAT_6: U26.U21(IO_L1N_T0_33) U35.N2(PDATA_6)
PDAT_7: U26.W21(IO_L4N_T0_33) U35.N1(PDATA_7)
PDAT_8: U26.AB21(IO_L8N_T1_33) U35.R1(PDATA_8)
PDAT_9: U26.U20(IO_L5P_T0_33) U35.R2(PDATA_9)
PDAT_10: U26.V20(IO_L5N_T0_33) U35.R3(PDATA_10)
PDAT_11: U26.W20(IO_L4P_T0_33) U35.P4(PDATA_11)
PDAT_12: U26.Y20(IO_L9P_T1_DQS_33) U35.R4(PDATA_12)
PDAT_13: U26.AB20(IO_L10N_T1_33) U35.P5(PDATA_13)
PDAT_14: U26.U19(IO_0_33) U35.R5(PDATA_14)
PDAT_15: U26.AB19(IO_L10P_T1_33) U35.P6(PDATA_15)
PDAT_16: U26.V17(IO_L16N_T2_33) U35.R6(PDATA_16)
PDAT_17: U26.AA17(IO_L17P_T2_33) U35.P7(PDATA_17)
PDAT_18: U26.AB17(IO_L17N_T2_33) U35.R7(PDATA_18)
PDAT_19: U26.U16(IO_L15N_T2_DQS_33) U35.P8(PDATA_19)
PDAT_20: U26.U15(IO_L15P_T2_DQS_33) U35.R8(PDATA_20)
PDAT_21: U26.U14(IO_25_33) U35.P9(PDATA_21)
PDAT_22: U26.V14(IO_L19P_T3_33) U35.R9(PDATA_22)
PDAT_23: U26.V13(IO_L20P_T3_33) U35.P10(PDATA_23)
PDAT_CLK: U26.W17(IO_L13P_T2_MRCC_33) U35.P3(PCLK)
PDAT_EN: U26.W13(IO_L20N_T3_33) U35.P2(DATEN_CMD)
PDAT_HS: U26.Y13(IO_L23P_T3_33) U35.N5(HSYNC_CS)
PDAT_MASK: R601.2(N2) U26.AA16(IO_L18P_T2_33) U35.N4(PDM_CVS_TE)
PDAT_VS: U26.Y14(IO_L22P_T3_33) U35.P1(VSYNC_WE)
RESETZ: TP32.1(P1) U35.C11(RESETZ) ; also on sheet 8 9 17
RREF: U35.F3(RREF)
SPI0_CLK: R83.1(N1) R579.1(N1) U33.6(CLK) ; also on sheet 9
SPI0_CSZ0: R86.1(N1) R577.2(N2) U33.1(~{CS}) ; also on sheet 9
SPI0_MISO: R576.2(N2) R578.1(N1) U35.B12(SPI0_DIN) ; also on sheet 9
SPI0_MOSI: R82.1(N1) U33.5(DIO) ; also on sheet 9
STAT_LED: D7.1(P1) R97.1(N1)
STAT_LEDDRV: R97.2(N2) U36.4(Y)
SUBFRAME_1: TP34.1(P1) U26.Y15(IO_L21N_T3_DQS_33) ; also on sheet 4
SUBFRAME_2: TP36.1(P1) U26.W15(IO_L21P_T3_DQS_33) ; also on sheet 4
TSTPT_2: TP50.1(P1) U35.R14(TSTPT_2) ; also on sheet 9
TSTPT_4: TP33.1(P1) U35.P14(TSTPT_4)
TSTPT_7: TP8.1(P1) U35.N15(TSTPT_7) ; also on sheet 4
N23637238: C13.2(N) R24.1(N1)
N23747793: R41.2(N2) U13.3(ON/OFFZ)
N23816315: Q2.3(DRAIN) R14.2(N2)

Not connected (* = marked no-connect by the designer): J13 1(P1) 2(P2) 3(P3) 4(P4) 5(P5) 6(P6) 7(P7) 8(P8) 9(P9) 10(P10) 11(P11) 12(P12) 13(P13) 14(P14) 15(P15) 16(P16) 17(P17) 18(P18) 19(P19) 20(P20) 21(P21) 22(P22) 23(P23) 24(P24) 26(P26); U13 4(NC)*; U20 J1(NC1)* J9(NC2)* L1(NC3)* L9(NC4)* M7(NC5)* T3(NC6)* T7(NC7)*; U26 AA1(PS_DDR_DQ26_502)* AA2(PS_DDR_DM3_502)* AA3(PS_DDR_DQ24_502)* AA13(IO_L23N_T3_33)* AA14(IO_L22N_T3_33)* AA18(IO_L12N_T1_MRCC_33)* AA19(IO_L11N_T1_SRCC_33)* AA21(IO_L8P_T1_33) AB16(IO_L18N_T2_33)* B15(IO_L7N_T1_AD2N_35) C15(IO_L7P_T1_AD2P_35) C17(IO_L11P_T1_SRCC_35) C18(IO_L11N_T1_SRCC_35) D15(IO_L3N_T0_DQS_AD1N_35) E15(IO_L3P_T0_DQS_AD1P_35) E16(IO_L1N_T0_AD0N_35) E18(IO_L5N_T0_AD9N_35) F4(PS_DDR_A13_502)* F16(IO_L1P_T0_AD0P_35) F17(IO_L6N_T0_VREF_35) F18(IO_L5P_T0_AD9P_35) F19(IO_L20N_T3_AD6N_35) F21(IO_L23P_T3_35) F22(IO_L23N_T3_35) G4(PS_DDR_A14_502)* G15(IO_L4P_T0_35) G16(IO_L4N_T0_35) G17(IO_L6P_T0_35) G19(IO_L20P_T3_AD6P_35) G20(IO_L22P_T3_AD7P_35) G21(IO_L22N_T3_AD7N_35) G22(IO_L24N_T3_AD15N_35) H17(IO_0_35) H18(IO_25_35) H19(IO_L19P_T3_35) H20(IO_L19N_T3_VREF_35) H22(IO_L24P_T3_AD15P_35) M1(PS_DDR_DQ16_502)* M2(PS_DDR_DQ22_502)* N2(PS_DDR_DQS_P2_502)* N3(PS_DDR_DQ18_502)* P1(PS_DDR_DM2_502)* P2(PS_DDR_DQS_N2_502)* R1(PS_DDR_DQ23_502)* R3(PS_DDR_DQ20_502)* T1(PS_DDR_DQ19_502)* T2(PS_DDR_DQ21_502)* T3(PS_DDR_DQ17_502)* U1(PS_DDR_DQ25_502)* U2(PS_DDR_DQ27_502)* U17(IO_L16P_T2_33) V2(PS_DDR_DQS_P3_502)* V15(IO_L19N_T3_VREF_33)* V18(IO_L6P_T0_33)* V19(IO_L6N_T0_VREF_33) W1(PS_DDR_DQ28_502)* W2(PS_DDR_DQS_N3_502)* W3(PS_DDR_DQ30_502)* W16(IO_L14P_T2_SRCC_33)* W18(IO_L13N_T2_MRCC_33)* Y1(PS_DDR_DQ31_502)* Y3(PS_DDR_DQ29_502)* Y16(IO_L14N_T2_SRCC_33)* Y19(IO_L11P_T1_SRCC_33)* Y21(IO_L9N_T1_DQS_33); U35 C1(DD3P) C2(DD3N) C12(SPI0_CSZ1) D1(DD2P) D2(DD2N) E1(DCLKP) E2(DCLKN) F1(DD1P) F2(DD1N) G1(DD0P) G2(DD0N) J1(PLL_REFCLK_O)* M13(JTAGTMS1)* N11(JTAGTMS2)* N12(JTAGTDO2)* N13(JTAGTDO1)* N14(TSTPT_6)* P12(JTAGTCK)* P13(JTAGTDI)* P15(TSTPT_5)* R12(TSTPT_0)* R13(TSTPT_1)* R15(TSTPT_3)*

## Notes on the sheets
sheet 11
- For Engineering
  Testing Only.
- 12V/3.0A
  Output
- For Engineering
  Testing Only.
- NOTE:
  THIS ACTUATOR DRIVER POWER CIRCUIT IS
  FOR THE ACTUATOR DRIVER CIRCUIT
  EXAMPLE ON PAGE 14.
  THE ACTUAL DRIVER POWER REQUIREMENTS
  FOR YOUR ACTUATOR IS SPECIFIED BY YOUR
  ACTUATOR  MANUFACTURER.
- For Engineering
  Testing Only.
- -12V/3.0A
  Output
- ACTUATOR DRIVER POWER
sheet 12
- VCCO_502 = P1P8V
- FRAME MEMORY
sheet 13
- VCCO_33 = P1P8V
- FPGA Parallel Data Output Interface
sheet 14
- CONNECTION TO FPD LINK VIDEO INPUT
  (PLACE ON TOP SIDE)
- TD2
- TC2
- TCLK2
- TB2
- TA2
- TD1
- TC1
- TCLK1
- TB1
- TA1
- VCCO_35 = P2P5V
sheet 15
- The DSI Port is not supported by
   the DLPC3436. Inputs are left
  unconnected  per datasheet
  recommendation.
- DLPC3436 ASIC, Clock,
  SPI Flash Memory & DSI
